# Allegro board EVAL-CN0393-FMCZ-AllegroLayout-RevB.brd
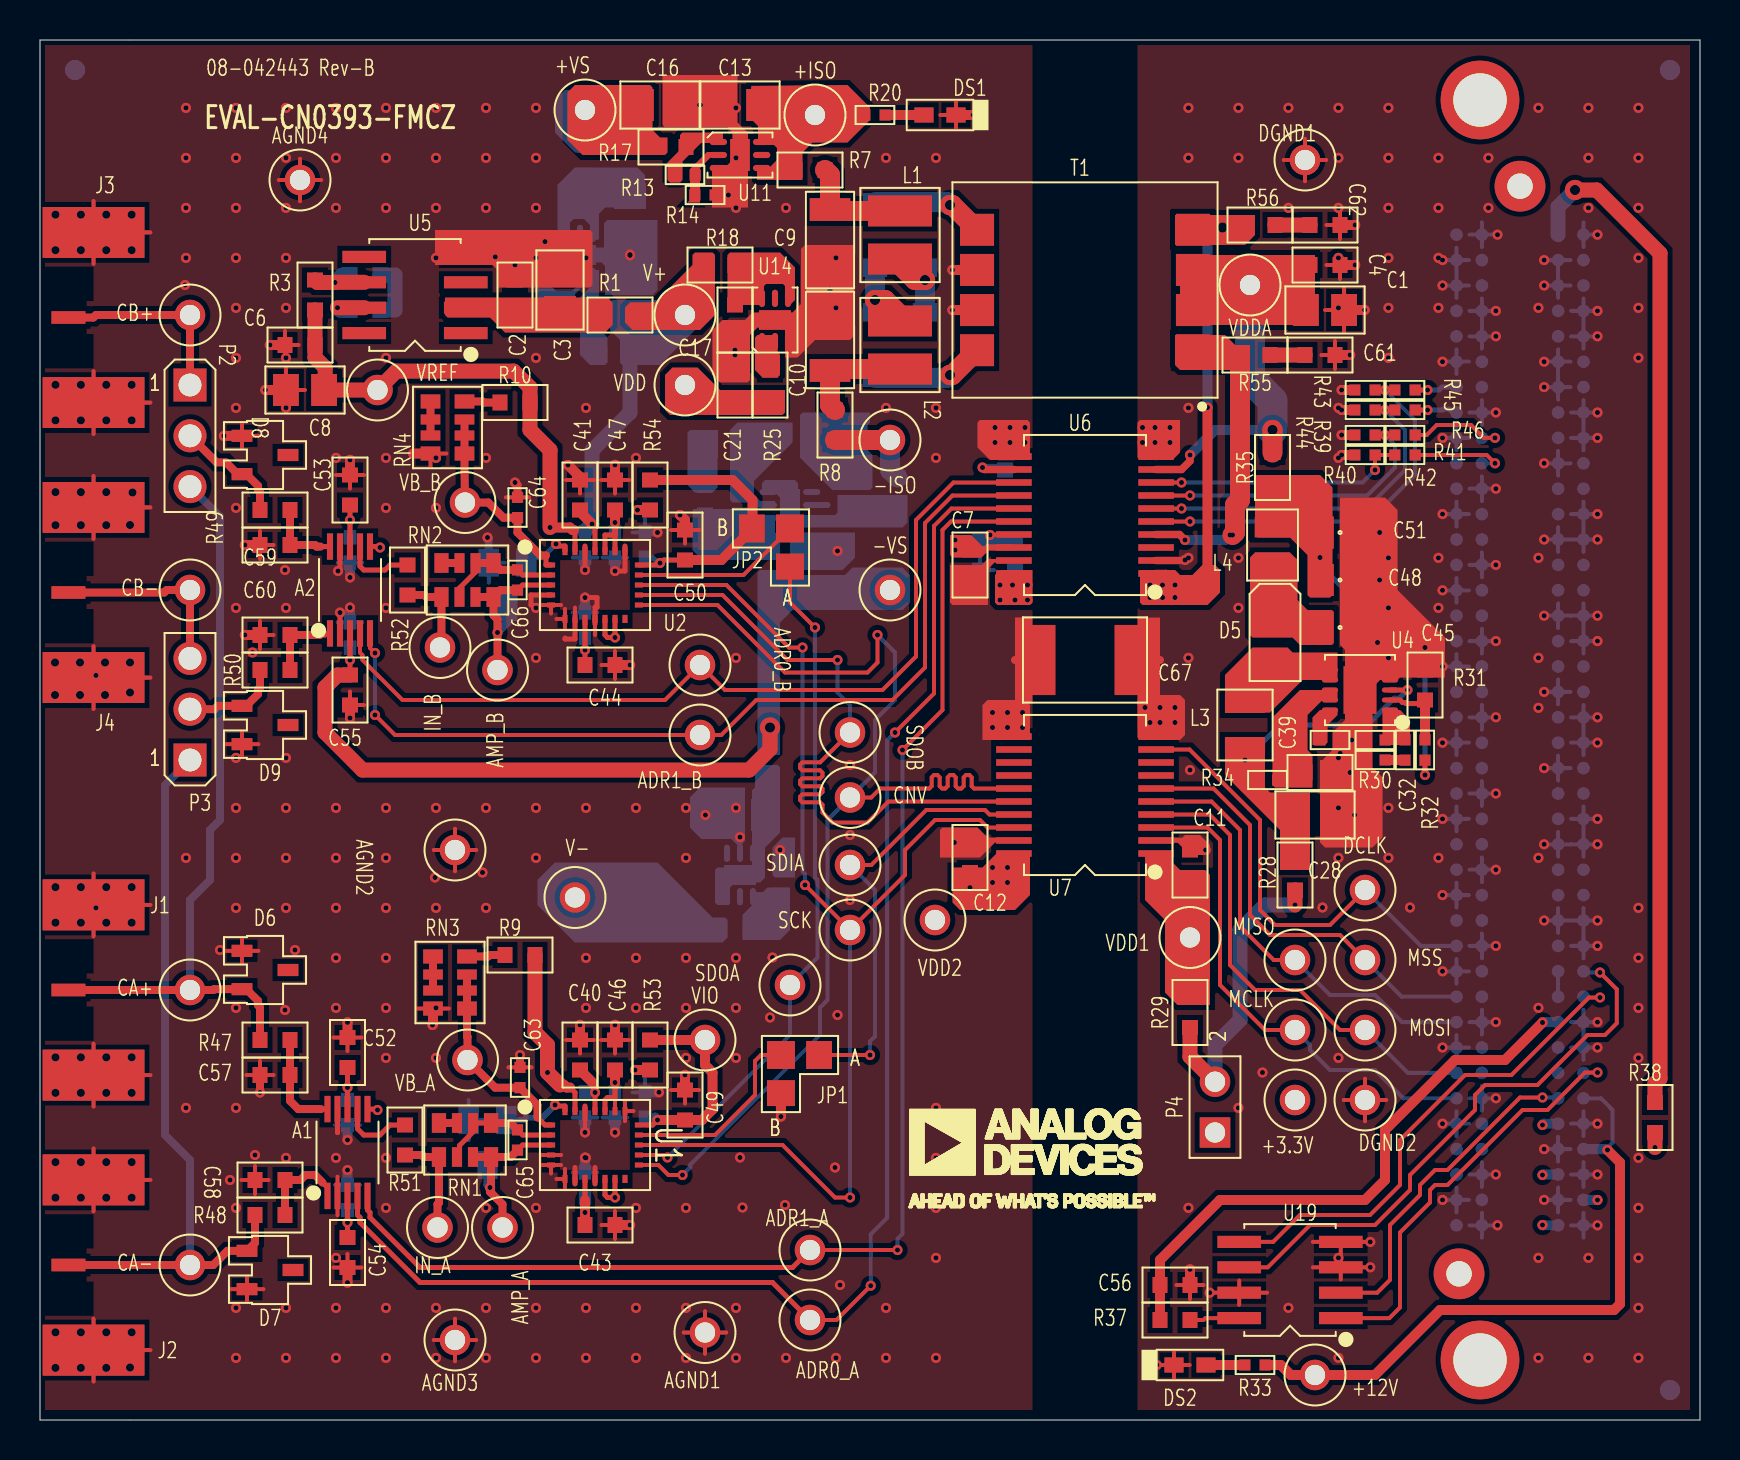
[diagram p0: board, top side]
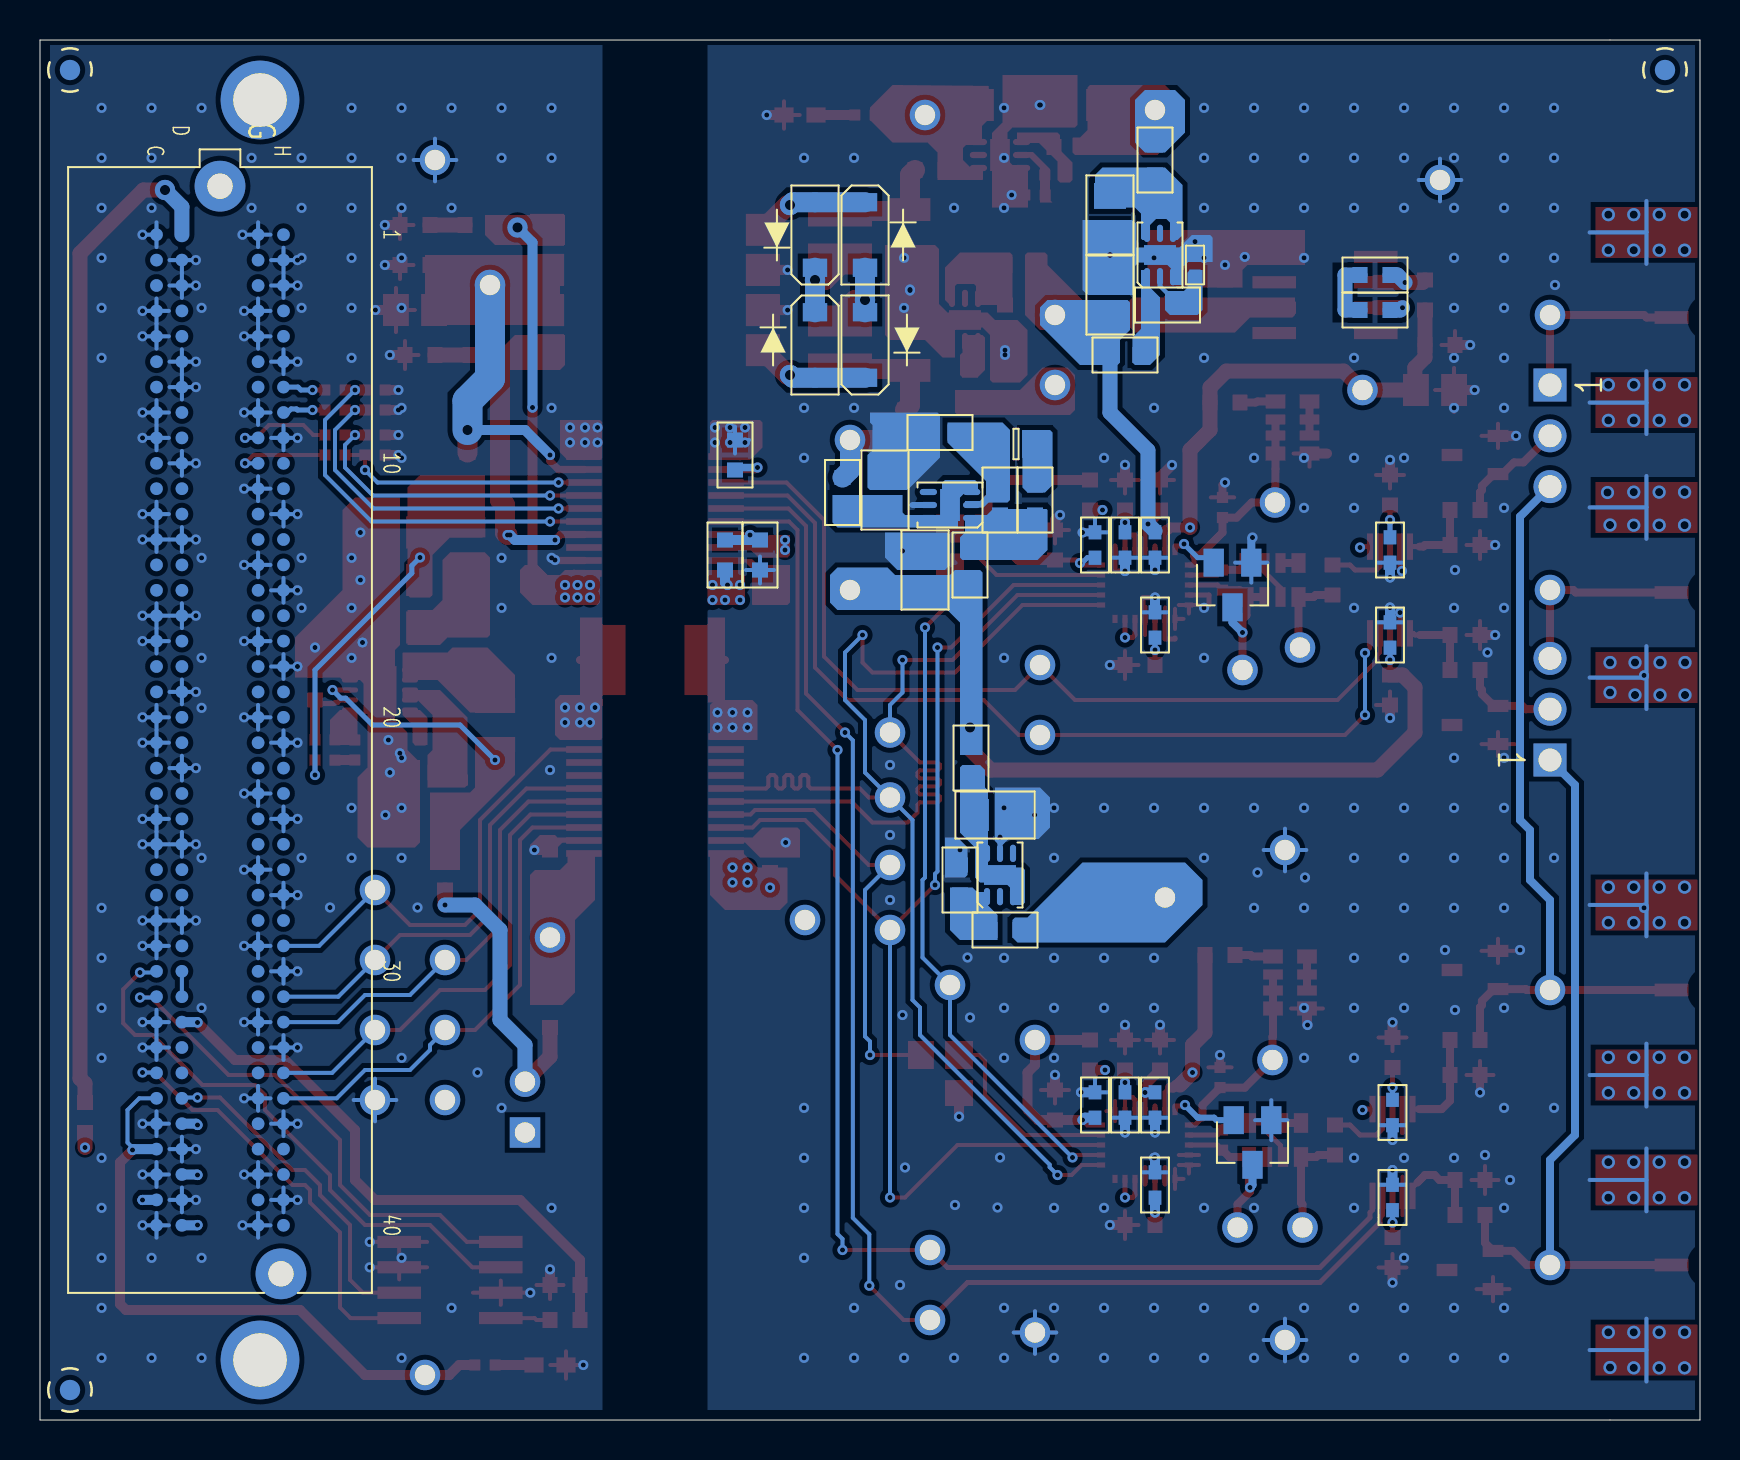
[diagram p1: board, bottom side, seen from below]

Outline 83 x 69 mm; copper layers: TOP, LAYER2, LAYER3, BOTTOM. Coordinates in mm from the lower left corner of the outline.
Outline path: 0,69 0,0 83,0 83,69 0,69

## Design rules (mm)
constraint set DEFAULT: 

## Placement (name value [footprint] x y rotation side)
A1  AD8251ARMZ  [RM10]  15.38 13.38 0 top
A2  AD8251ARMZ  [RM10]  15.5 41.5 0 top
ADR0_A  RED  [CNKEY5001TP]  38.5 5 0 top
ADR0_B  RED  [CNKEY5001TP]  33 37.75 0 top
ADR1_A  RED  [CNKEY5001TP]  38.5 8.5 0 top
ADR1_B  RED  [CNKEY5001TP]  33 34.25 0 top
AGND1  BLK  [CNKEY5001TP]  33.25 4.38 0 top
AGND2  BLK  [CNKEY5001TP]  20.75 28.5 0 top
AGND3  BLK  [CNKEY5001TP]  20.75 4 0 top
AGND4  BLK  [CNKEY5001TP]  13 62 0 top
AMP_A  RED  [CNKEY5001TP]  23.12 9.62 0 top
AMP_B  RED  [CNKEY5001TP]  22.88 37.5 0 top
C1  10uF  [C0805H53]  64.25 55.5 0 top
C2  0.1uF  [C0603]  23.75 56.25 90 top
C3  10uF  [C0805H53]  26 56.5 90 top
C4  0.1uF  [C0603]  64.25 57.75 0 top
C5  0.0027uF  [C0603]  16.25 57.25 0 bottom
C6  0.1uF  [C0603]  13 53.75 180 top
C7  0.1uF  [C0603]  46.5 42.75 270 top
C8  10uF  [C0805H53]  13.25 51.5 180 top
C9  47uF  [C1206H71]  39.5 59 270 top
C10  47uF  [C1206H71]  39.5 54 270 top
C11  0.1uF  [C0603]  57.5 27.75 90 top
C12  0.1uF  [C0603]  46.5 28.12 270 top
C13  10UF  [C0805H53]  35 65.75 180 top
C14  10UF  [C0805H53]  40.75 46.5 90 bottom
C15  0.1uF  [C0603]  33.25 46 270 bottom
C16  10UF  [C0805H53]  31 65.75 0 top
C17  4.7uF  [C0603]  34.75 55 270 top
C18  10UF  [C0805H53]  38.75 42.5 90 bottom
C19  4.7uF  [C0805H53]  29.5 60.25 270 bottom
C20  1uF  [C0805H53]  35.25 30.25 180 bottom
C21  4.7uF  [C0603]  34.75 51.75 90 top
C22  4.7uF  [C0603]  37 27 90 bottom
C23  10UF  [C0805H53]  29.5 56.25 90 bottom
C24  0.1uF  [C0402_A]  27.25 15.75 270 bottom
C25  0.1uF  [C0402_A]  27.25 43.75 270 bottom
C26  0.1uF  [C0402_A]  27.25 11.75 90 bottom
C27  0.1uF  [C0402_A]  27.25 39.75 90 bottom
C28  10UF  [C0805H53]  63.75 30.25 0 top
C29  10pF  [C0402]  66.75 34 0 top
C30  0.1uF  [C0402_A]  28.75 15.75 270 bottom
C31  0.1uF  [C0402_A]  28.75 43.75 270 bottom
C32  0.0068uF  [C0402]  68.25 33.5 270 top
C33  0.1uF  [C0402_A]  30.25 15.75 90 bottom
C34  0.1uF  [C0402_A]  30.25 43.75 90 bottom
C35  0.1uF  [C0402_A]  15.38 15.38 270 bottom
C36  0.1uF  [C0402_A]  15.5 43.5 270 bottom
C37  0.1uF  [C0402_A]  15.38 11.12 90 bottom
C38  0.1uF  [C0402_A]  15.5 39.25 90 bottom
C39  1uF  [C0603]  64 32.38 0 top
C40  10uF  [C0603]  27 18.25 90 top
C41  10uF  [C0603]  27 46.25 90 top
C42  0.01UF  [C0402]  64.5 34 0 top
C43  10uF  [C0603]  28 9.75 0 top
C44  10uF  [C0603]  28 37.75 0 top
C45  0.47uF  [C0805]  65 39.62 0 top
C46  10uF  [C0603]  28.75 18.25 90 top
C47  10uF  [C0603]  28.75 46.25 90 top
C48  10uF  [C0805]  65 42 0 top
C49  10uF  [C0603]  32.25 15.75 90 top
C50  10uF  [C0603]  32.25 43.75 90 top
C51  10uF  [C0805]  65 44.38 0 top
C52  10uF  [C0603]  15.38 18.38 90 top
C53  10uF  [C0603]  15.5 46.5 90 top
C54  10uF  [C0603]  15.38 8.38 270 top
C55  10uF  [C0603]  15.5 36.5 270 top
C56  0.1uF  [C0603]  56.75 6.75 0 top
C57  2.2uF  [C0603]  11.75 17.25 180 top
C58  2.2uF  [C0603]  11.5 12 180 top
C59  2.2uF  [C0603]  11.75 43.75 180 top
C60  2.2uF  [C0603]  11.75 39.25 180 top
C61  330pF  [C0603]  64 53.25 0 top
C62  330pF  [C0603]  64.25 59.75 0 top
C63  1.5PF  [C0402]  24 17.12 90 top
C64  1.5PF  [C0402]  23.88 45.62 90 top
C65  1.5PF  [C0402]  23.88 14 270 top
C66  1.5PF  [C0402]  23.88 42 270 top
C67  100PF  [C1812H63]  52.25 38 180 top
CA+  RED  [CNKEY5001TP]  7.5 21.5 0 top
CA-  RED  [CNKEY5001TP]  7.5 7.75 0 top
CB+  RED  [CNKEY5001TP]  7.5 55.25 0 top
CB-  RED  [CNKEY5001TP]  7.5 41.5 0 top
CNV  RED  [CNKEY5001TP]  40.5 31.12 0 top
CR1  BAT54S  [SOT23]  22.38 13.88 0 bottom
CR2  BAT54S  [SOT23]  23.38 41.75 0 bottom
D1  MBR0540T1G  [SOD123-2]  44.25 53.75 270 bottom
D2  MBR0540T1G  [SOD123-2]  41.75 53.75 90 bottom
D3  MBR0540T1G  [SOD123-2]  44.25 59.25 90 bottom
D4  MBR0540T1G  [SOD123-2]  41.75 59.25 270 bottom
D5  DFLS220L-7  [DSML110W70H39]  61.75 39.38 270 top
D6  MMBZ15VDL-7-F  [SOT23_B]  11.25 22.5 270 top
D7  MMBZ15VDL-7-F  [SOT23_B]  11.5 7.5 270 top
D8  MMBZ15VDL-7-F  [SOT23_B]  11.25 48.25 270 top
D9  MMBZ15VDL-7-F  [SOT23_B]  11.25 34.75 270 top
DCLK  RED  [CNKEY5001TP]  66.25 26.5 0 top
DGND1  BLK  [CNKEY5001TP]  63.25 63 0 top
DGND2  BLK  [CNKEY5001TP]  66.25 16 0 top
DS1  SML-310MTT86  [LED0603]  45 65.25 180 top
DS2  SML-310MTT86  [LED0603]  57.5 2.75 0 top
IN_A  RED  [CNKEY5001TP]  19.88 9.62 0 top
IN_B  RED  [CNKEY5001TP]  20 38.62 0 top
J1  142-0701-851  [CNSMAL562W375H166]  2.5 21.5 180 top
J2  142-0701-851  [CNSMAL562W375H166]  2.5 7.75 180 top
J3  142-0701-851  [CNSMAL562W375H166]  2.5 55.12 180 top
J4  142-0701-851  [CNSMAL562W375H166]  2.5 41.38 180 top
JP1  3PIN_JUMPER_SM  [3PINJUMPER_0603]  38 18.25 180 top
JP2  3PIN_JUMPER_SM  [3PINJUMPER_0603]  37.5 43.62 90 top
L1  47UH  [L1212H59_A]  43 59.25 90 top
L2  47UH  [L1212H59_A]  43 53.75 270 top
L3  1UH  [L1008H47]  60.25 34.75 90 top
L4  110nH  [L9075]  61.62 43.75 90 top
MCLK  RED  [CNKEY5001TP]  62.75 19.5 0 top
MISO  RED  [CNKEY5001TP]  62.75 23 0 top
MOSI  RED  [CNKEY5001TP]  66.25 19.5 0 top
MSS  RED  [CNKEY5001TP]  66.25 23 0 top
NOREF  -  []  0 69 0 top
NOREF#2  -  [unnamed#2]  72 66 0 top
NOREF#3  -  []  -54 -78 0 top
NOREF#4  -  [unnamed#2]  72 3 0 top
NOREF#5  -  []  0 0 90 top
NOREF#6  -  []  58 -10.5 0 top
NOREF#7  -  []  -54 -78 0 top
NOREF#8  -  [unnamed#2]  81.5 1.5 180 bottom
NOREF#9  -  [unnamed#2]  81.5 67.5 180 bottom
NOREF#10  -  [unnamed#2]  1.75 67.5 180 bottom
P1  ASP-134604-01  [CNSAMTECASP-134604-01]  74 34.5 270 bottom
P2  TSW-103-08-G-S  [CNBERG1X3H205LD36]  7.5 51.75 270 top
P3  TSW-103-08-G-S  [CNBERG1X3H205LD36]  7.5 33 90 top
P4  69157-102HLF  [CNBERG69157-102]  58.75 14.38 90 top
R1  0  [R0603]  29 55.25 180 top
R2  0  [R0603]  16.25 55.5 0 bottom
R3  0  [R0603]  13.75 56.25 270 top
R4  100K  [R0603]  48.25 48.25 90 bottom
R5  100K  [R0603]  48.75 43.25 90 bottom
R6  8.2K  [R0603]  47 43.25 270 bottom
R7  0  [R0603]  38.5 62.5 180 top
R8  0  [R0603]  39.75 49.75 270 top
R9  0  [R0603]  24 23.25 180 top
R10  0  [R0603]  23.75 50.88 180 top
R11  0  [R0603]  42.88 46.38 270 bottom
R12  13.3K  [R0603]  38 49.38 180 bottom
R13  100K  [R0402]  32.25 62.25 180 top
R14  49.9K  [R0402]  33.25 61.25 0 top
R15  13K  [R0805]  34.2 48.8 180 bottom
R16  150K  [R0603]  35 46 270 bottom
R17  0  [R0603]  31.55 63.65 180 top
R18  0  [R0603]  34 57.75 0 top
R19  0  [R0603]  36.5 42.75 270 bottom
R20  100K  [R0402]  41.75 65.25 0 top
R21  0  [R0603]  27.25 63 270 bottom
R22  0  [R0603]  36.45 33.1 270 bottom
R23  25K  [R0603]  26.62 55.75 0 bottom
R24  49.9K  [R0402]  25.25 57.75 90 bottom
R25  0  [R0603]  36.5 51.75 270 top
R26  0  [R0603]  28.75 53.25 0 bottom
R27  0  [R0603]  34.75 24.5 180 bottom
R28  0  [R0603]  62.75 27.25 90 top
R29  0  [R0603]  57.5 20.38 90 top
R30  2.94K  [R0402]  66.75 33 0 top
R31  31.6K  [R0603]  69.25 36.75 270 top
R32  95.3K  [R0402]  69.25 33.5 270 top
R33  49.9K  [R0402]  60.75 2.75 0 top
R34  1  [R0402]  61.38 32 0 top
R35  0  [R0603]  61.62 47.62 90 top
R37  0  [R0603]  56.75 5 180 top
R38  10K  [R0603]  80.75 15.12 90 top
R39  0  [R0402]  66.25 49.25 0 top
R40  0  [R0402]  66.25 48.25 180 top
R41  0  [R0402]  68.25 49.25 0 top
R42  0  [R0402]  68.25 48.25 0 top
R43  0  [R0402]  66.25 51.5 0 top
R44  0  [R0402]  66.25 50.5 180 top
R45  0  [R0402]  68.25 51.5 0 top
R46  0  [R0402]  68.25 50.5 0 top
R47  0  [R0603]  11.75 19 0 top
R48  0  [R0603]  11.5 10.25 0 top
R49  0  [R0603]  11.75 45.5 0 top
R50  0  [R0603]  11.75 37.5 0 top
R51  0  [R0603]  18.25 14 270 top
R52  0  [R0603]  18.38 42 270 top
R53  0  [R0603]  30.5 18.25 90 top
R54  0  [R0603]  30.5 46.25 90 top
R55  14  [R0603]  60.75 53.25 0 top
R56  14  [R0603]  61 59.75 0 top
RN1  1K  [R1206-8P]  21.25 14 180 top
RN2  1K  [R1206-8P]  21.38 42 180 top
RN3  1K  [R1206-8P]  20.5 21.88 270 top
RN4  1K  [R1206-8P]  20.38 49.62 270 top
SCK  RED  [CNKEY5001TP]  40.5 24.5 0 top
SDIA  RED  [CNKEY5001TP]  40.5 27.75 0 top
SDOA  RED  [CNKEY5001TP]  37.5 21.75 0 top
SDOB  RED  [CNKEY5001TP]  40.5 34.38 0 top
T1  KA4976-AL  [TSML394W319H235]  52.25 56.5 90 top
U1  ADAQ7988BCCZ  [LGA24]  27.75 13.75 270 top
U2  ADAQ7988BCCZ  [LGA24]  27.75 41.75 270 top
U3  ADP7182ACPZN  [DFN6_2X2_PAD1_6X1]  37.5 45.75 90 bottom
U4  ADP1614ACPZ-R7  [QFN10_3X3_PAD2_38X1_64]  66 36.5 90 top
U5  ADR4550BRZ  [SO8]  18.75 56.25 90 top
U6  ADUM3470ARSZ  [SSOP20-4]  52.25 45.25 90 top
U7  ADUM3150ARSZ  [SSOP20-4]  52.25 31.25 90 top
U11  ADP7118ACPZN-5.0  [DFN6_2X2_PAD1_6X1]  35 63.25 270 top
U13  ADP7118ACPZN-5.0  [DFN6_2X2_PAD1_6X1]  27 58.25 180 bottom
U14  ADP7118ACPZN-5.0  [DFN6_2X2_PAD1_6X1]  36.75 55 0 top
U17  ADP7182ACPZN-2.5  [DFN6_2X2_PAD1_6X1]  35 27.25 180 bottom
U19  M24C02-RMN6TP  [SO8]  62.5 7 90 top
UNK+3.3V  RED  [CNKEY5001TP]  62.75 16 0 top
UNK+12V  RED  [CNKEY5001TP]  63.75 2.25 0 top
UNK+ISO  RED  [CNKEY5001TP]  38.75 65.25 0 top
UNK+VS  RED  [CNKEY5001TP]  27.25 65.5 0 top
UNK-ISO  RED  [CNKEY5001TP]  42.5 49 0 top
UNK-VS  RED  [CNKEY5001TP]  42.5 41.5 0 top
V+  RED  [CNKEY5001TP]  32.25 55.25 0 top
V-  RED  [CNKEY5001TP]  26.75 26.12 0 top
VB_A  RED  [CNKEY5001TP]  21.38 18 0 top
VB_B  RED  [CNKEY5001TP]  21.25 45.88 0 top
VDD  RED  [CNKEY5001TP]  32.25 51.75 0 top
VDD1  RED  [CNKEY5001TP]  57.5 24.12 0 top
VDD2  RED  [CNKEY5001TP]  44.75 25 0 top
VDDA  RED  [CNKEY5001TP]  60.5 56.75 0 top
VIO  RED  [CNKEY5001TP]  33.25 19 0 top
VREF  RED  [CNKEY5001TP]  16.88 51.5 0 top

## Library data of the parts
A1 A2 = AD8251: User Part Number: UPN; Tolerance: N/A; alternate symbols: (); part number: AD8251_SM-AD8251ARMZ,E019018,RM10; tolerance: N/A
ADR0_A ADR0_B ADR1_A ADR1_B AMP_A AMP_B CA+ CA- CB+ CB- CNV DCLK IN_A IN_B MCLK MISO MOSI MSS SCK SDIA SDOA SDOB UNK+3.3V UNK+12V UNK+ISO UNK+VS UNK-ISO UNK-VS V+ V- VB_A VB_B VDD VDD1 VDD2 VDDA VIO VREF = CNTP1P: Tolerance: N/A; User Part Number: UPN; alternate symbols: (); part number: CNTP1P_TH-RED,E019485,CNKEY5001TP; tolerance: N/A
AGND1-AGND4 DGND1 DGND2 = CNTP1P: Tolerance: N/A; User Part Number: UPN; alternate symbols: (); part number: CNTP1P_TH-BLK,E019484,CNKEY5001TP; tolerance: N/A
C1 C3 C8 = CAP: User Part Number: UPN; Tolerance: 10; alternate symbols: (); part number: CAP_SM-10UF,16V,10,E006166,C0805H53; tolerance: 10
C2 C4 C6 C7 C11 C12 C56 = CAP: User Part Number: UPN; Tolerance: 10; alternate symbols: (); part number: CAP_SM-0.1UF,16V,10,E015036,C0603; tolerance: 10
C5 = CAP: User Part Number: UPN; Tolerance: 10; alternate symbols: (); part number: CAP_SM-0.0027UF,50V,10,E015578,C0603; tolerance: 10
C9 C10 = CAP: User Part Number: UPN; Tolerance: 20; alternate symbols: (); part number: CAP_SM-47UF,25V,20,E019173,C1206H71; tolerance: 20
C13 C14 C16 C18 C23 C28 = CAP: User Part Number: UPN; Tolerance: 10; alternate symbols: (); part number: CAP_SM-10UF,35V,10,E025307,C0805H53; tolerance: 10
C15 = CAP: User Part Number: UPN; Tolerance: 10; alternate symbols: (); part number: CAP_SM-0.1UF,25V,10,E013746,C0603; tolerance: 10
C17 C21 C22 = CAP: User Part Number: UPN; Tolerance: 10; alternate symbols: (); part number: CAP_SM-4.7UF,16V,10,E020112,C0603; tolerance: 10
C19 = CAP: User Part Number: UPN; Tolerance: 10; alternate symbols: (); part number: CAP_SM-4.7UF,25V,10,E006908,C0805H53; tolerance: 10
C20 = CAP: User Part Number: UPN; Tolerance: 10; alternate symbols: (); part number: CAP_SM-1UF,25V,10,E023500,C0805H53; tolerance: 10
C24-C27 C30 C31 C33-C38 = CAP: Tolerance: 10; User Part Number: UPN; alternate symbols: (); part number: CAP_SM-0.1UF,25V,10,E020372,C0402_A; tolerance: 10
C29 = CAP: User Part Number: UPN; Tolerance: 5; alternate symbols: (); part number: CAP_SM-10PF,50V,5,E007982,C0402; tolerance: 5
C32 = CAP: User Part Number: UPN; Tolerance: 10; alternate symbols: (); part number: CAP_SM-0.0068UF,25V,10,E012594,C0402; tolerance: 10
C39 = CAP: User Part Number: UPN; Tolerance: 10; alternate symbols: (); part number: CAP_SM-1UF,10V,10,E011783,C0603; tolerance: 10
C40 C41 C43 C44 C46 C47 C49 C50 C52-C55 = CAP: User Part Number: UPN; Tolerance: 20; alternate symbols: (); part number: CAP_SM-10UF,25V,20,E023693,C0603; tolerance: 20
C42 = CAP: User Part Number: UPN; Tolerance: 10; alternate symbols: (); part number: CAP_SM-0.01UF,25V,10,E013688,C0402; tolerance: 10
C45 = CAP: User Part Number: UPN; Tolerance: 10; alternate symbols: (); part number: CAP_SM-0.47UF,16V,10,E000566,C0805; tolerance: 10
C48 C51 = CAP: User Part Number: UPN; Tolerance: 10; alternate symbols: (); part number: CAP_SM-10UF,25V,10,E019080,C0805; tolerance: 10
C57-C60 = CAP: User Part Number: UPN; Tolerance: 10; alternate symbols: (); part number: CAP_SM-2.2UF,6.3V,10,E006877,C0603; tolerance: 10
C61 C62 = CAP: User Part Number: UPN; Tolerance: 5; alternate symbols: (); part number: CAP_SM-330PF,50V,5,E012696,C0603; tolerance: 5
C63-C66 = CAP: User Part Number: UPN; Tolerance: 0.25PF; alternate symbols: (); part number: CAP_SM-1.5PF,50V,0.25PF,E000262,C0402; tolerance: 0.25PF
C67 = CAP: Tolerance: 10; User Part Number: UPN; alternate symbols: (); part number: CAP_SM-100PF,3000V,10,E026062,C1812H63; tolerance: 10
CR1 CR2 = DIOHSMS28X2: User Part Number: UPN; Tolerance: N/A; alternate symbols: (); part number: DIOHSMS28X2_SM-BAT54S,30V,N/A,E006846,SOT23; tolerance: N/A
D1-D4 = DIOSCHOTTKY: User Part Number: UPN; Tolerance: N/A; alternate symbols: (); part number: DIOSCHOTTKY_SM-MBR0540T1G,40V,N/A,E011535,SOD123-2; tolerance: N/A
D5 = DIOSCHOTTKY: User Part Number: UPN; Tolerance: N/A; alternate symbols: (); part number: DIOSCHOTTKY_SM-DFLS220L-7,20V,N/A,E010878,DSML110W70H39; tolerance: N/A
D6-D9 = DIOTVS3P: User Part Number: UPN; Tolerance: N/A; alternate symbols: (); part number: DIOTVS3P_SM-MMBZ15VDL-7-F,12.8V,N/A,E025412,SOT23_B; tolerance: N/A
DS1 DS2 = DIOLED: User Part Number: UPN; Tolerance: N/A; alternate symbols: (); part number: DIOLED_SM-SML-310MTT86,2.8V,N/A,E001179,LED0603; tolerance: N/A
J1-J4 = CNBNC5P: Tolerance: N/A; User Part Number: UPN; alternate symbols: (); part number: CNBNC5P_SM-142-0701-851,E014551,CNSMAL562W375H166; tolerance: N/A
JP1 JP2 = NC3P_JMPR: User Part Number: UPN; Tolerance: N/A; alternate symbols: (); part number: NC3P_JMPR_SM-3PIN_JUMPER_SM,E008052,3PINJUMPER_0603; tolerance: N/A
L1 L2 = IND: User Part Number: UPN; Tolerance: 20; alternate symbols: (); part number: IND_SM-47UH,20,E017337,L1212H59_A; tolerance: 20
L3 = IND: Tolerance: 20; User Part Number: UPN; alternate symbols: (); part number: IND_SM-1UH,20,E025308,L1008H47; tolerance: 20
L4 = IND: Tolerance: 5; User Part Number: UPN; alternate symbols: (); part number: IND_SM-110NH,5,E016398,L9075; tolerance: 5
P1 = CN160P_CDGH: User Part Number: UPN; Tolerance: N/A; alternate symbols: (CNSAMTECASP-134604-01_KITTRF); part number: CN160P_CDGH_SM-ASP-134604-01,E011383,CNSAMTECASP-134604-01; tolerance: N/A
P2 P3 = CN3P: Tolerance: N/A; User Part Number: UPN; alternate symbols: (); part number: CN3P_TH-TSW-103-08-G-S,E000812,CNBERG1X3H205LD36; tolerance: N/A
P4 = CN2P: User Part Number: UPN; Tolerance: N/A; alternate symbols: (); part number: CN2P_TH-69157-102HLF,E000791,CNBERG69157-102; tolerance: N/A
R1-R3 R7-R11 R17-R19 R21 R22 R25-R29 R35 R37 R47-R54 = RES: User Part Number: UPN; Tolerance: 1; alternate symbols: (); part number: RES_SM-0,E004207,1/16W,1,R0603; tolerance: 1
R4 R5 = RES: User Part Number: UPN; Tolerance: 1; alternate symbols: (); part number: RES_SM-100K,E010279,1/10W,1,R0603; tolerance: 1
R6 = RES: User Part Number: UPN; Tolerance: 1; alternate symbols: (); part number: RES_SM-8.2K,E004253,1/16W,1,R0603; tolerance: 1
R12 = RES: User Part Number: UPN; Tolerance: 1; alternate symbols: (); part number: RES_SM-13.3K,E008069,1/10W,1,R0603; tolerance: 1
R13 R20 = RES: User Part Number: UPN; Tolerance: 5; alternate symbols: (); part number: RES_SM-100K,E003464,1/10W,5,R0402; tolerance: 5
R14 R24 R33 = RES: User Part Number: UPN; Tolerance: 1; alternate symbols: (); part number: RES_SM-49.9K,E004901,1/16W,1,R0402; tolerance: 1
R15 = RES: User Part Number: UPN; Tolerance: 1; alternate symbols: (); part number: RES_SM-13K,E003507,1/8W,1,R0805; tolerance: 1
R16 = RES: User Part Number: UPN; Tolerance: 1; alternate symbols: (); part number: RES_SM-150K,E003672,1/10W,1,R0603; tolerance: 1
R23 = RES: User Part Number: UPN; Tolerance: 0.1; alternate symbols: (); part number: RES_SM-25K,E018041,0.15W,0.1,R0603; tolerance: 0.1
R30 = RES: User Part Number: UPN; Tolerance: 1; alternate symbols: (); part number: RES_SM-2.94K,E018093,1/10W,1,R0402; tolerance: 1
R31 = RES: User Part Number: UPN; Tolerance: 1; alternate symbols: (); part number: RES_SM-31.6K,E013702,1/10W,1,R0603; tolerance: 1
R32 = RES: User Part Number: UPN; Tolerance: 1; alternate symbols: (); part number: RES_SM-95.3K,E006343,1/16W,1,R0402; tolerance: 1
R34 = RES: User Part Number: UPN; Tolerance: 5; alternate symbols: (); part number: RES_SM-1,E010031,1/16W,5,R0402; tolerance: 5
R38 = RES: User Part Number: UPN; Tolerance: 1; alternate symbols: (); part number: RES_SM-10K,E003671,1/10W,1,R0603; tolerance: 1
R39-R46 = RES: User Part Number: UPN; Tolerance: 5; alternate symbols: (); part number: RES_SM-0,E003438,N/A,5,R0402; tolerance: 5
R55 R56 = RES: User Part Number: UPN; Tolerance: 1; alternate symbols: (); part number: RES_SM-14,E025536,1/10W,1,R0603; tolerance: 1
RN1-RN4 = RESNET_8P_4R: Tolerance: 0.1; User Part Number: UPN; alternate symbols: (); part number: RESNET_8P_4R_SM-1K,E024992,1/10W,0.1,R1206-8P; tolerance: 0.1
T1 = XFMRKA4976: Tolerance: N/A; User Part Number: UPN; alternate symbols: (); part number: XFMRKA4976_SM-KA4976-AL,E017329,TSML394W319H235; tolerance: N/A
U1 U2 = ADAQ798X: Tolerance: N/A; User Part Number: UPN; alternate symbols: (); part number: ADAQ798X_SM-ADAQ7988BCCZ,E028182,LGA24; tolerance: N/A
U3 = ADP7182_V5: Tolerance: N/A; User Part Number: UPN; alternate symbols: (); part number: ADP7182_V5_SM-ADP7182ACPZN,E024308,DFN6_2X2_PAD1_6X1; tolerance: N/A
U4 = ADP1614: User Part Number: UPN; Tolerance: N/A; alternate symbols: (); part number: ADP1614_SM-ADP1614ACPZ-R7,E025247,QFN10_3X3_PAD2_38X1_64; tolerance: N/A
U5 = ADR45XX: User Part Number: UPN; Tolerance: N/A; alternate symbols: (); part number: ADR45XX_SM-ADR4550BRZ,E016255,SO8; tolerance: N/A
U6 = ADUM3470: Tolerance: N/A; User Part Number: UPN; alternate symbols: (); part number: ADUM3470_SM-ADUM3470ARSZ,E024958,SSOP20-4; tolerance: N/A
U7 = ADUM3150: Tolerance: N/A; User Part Number: UPN; alternate symbols: (); part number: ADUM3150_SM-ADUM3150ARSZ,E021747,SSOP20-4; tolerance: N/A
U11 U13 U14 = ADP7118: Tolerance: N/A; User Part Number: UPN; alternate symbols: (); part number: ADP7118_SM-ADP7118ACPZN-5.0,E021288,DFN6_2X2_PAD1_6X1; tolerance: N/A
U17 = ADP7182_V6: Tolerance: N/A; User Part Number: UPN; alternate symbols: (); part number: ADP7182_V6_SM-ADP7182ACPZN-2.5,E024945,DFN6_2X2_PAD1_6X1; tolerance: N/A
U19 = ICM24CXX: User Part Number: UPN; Tolerance: N/A; alternate symbols: (); part number: ICM24CXX_SM-M24C02-RMN6TP,E018349,SO8; tolerance: N/A

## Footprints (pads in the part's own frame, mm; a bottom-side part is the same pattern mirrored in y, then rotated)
3PINJUMPER_0603
  rect 1.295x1.397 smd: 1(-0.953,0)
  rect 1.397x1.397 smd: 2(0.953,0)
  rect 1.397x1.295 smd: 3(0.953,1.905)
C0402
  rect 0.559x0.559 smd: 1(-0.508,0) 2(0.508,0)
C0402_A
  rect 0.711x0.635 smd: 1(-0.635,0) 2(0.635,0)
C0603
  rect 0.75x0.8 smd: 1(-0.75,0) 2(0.75,0)
C0805
  rect 1.295x1.6 smd: 1(-0.953,0) 2(0.953,0)
C0805H53
  rect 1.295x1.6 smd: 1(-0.953,0) 2(0.953,0)
C1206H71
  rect 1.143x2.032 smd: 1(-1.524,0) 2(1.524,0)
C1812H63
  rect 1.245x3.505 smd: 1(-2.1,0) 2(2.1,0)
CNBERG1X3H205LD36
  rect 1.651x1.651 hole 1.143: 1(0,0)
  round 1.651 hole 1.143: 2(2.54,0) 3(5.08,0)
CNBERG69157-102
  rect 1.524x1.524 hole 1.016: 1(0,0)
  round 1.524 hole 1.016: 2(2.54,0)
CNKEY5001TP
  round 1.524 hole 1.016: 1(0,0)
CNSAMTECASP-134604-01
  round 2.54 hole 1.27 unplated: (-27.191,0) (27.191,3.048)
  round 0.635 smd: C1(-24.765,-3.175) C2(-23.495,-3.175) C3(-22.225,-3.175) C4(-20.955,-3.175) C5(-19.685,-3.175) C6(-18.415,-3.175) C7(-17.145,-3.175) C8(-15.875,-3.175) C9(-14.605,-3.175) C10(-13.335,-3.175) C11(-12.065,-3.175) C12(-10.795,-3.175) C13(-9.525,-3.175) C14(-8.255,-3.175) C15(-6.985,-3.175) C16(-5.715,-3.175) C17(-4.445,-3.175) C18(-3.175,-3.175) C19(-1.905,-3.175) C20(-0.635,-3.175) C21(0.635,-3.175) C22(1.905,-3.175) C23(3.175,-3.175) C24(4.445,-3.175) C25(5.715,-3.175) C26(6.985,-3.175) C27(8.255,-3.175) C28(9.525,-3.175) C29(10.795,-3.175) C30(12.065,-3.175) C31(13.335,-3.175) C32(14.605,-3.175) C33(15.875,-3.175) C34(17.145,-3.175) C35(18.415,-3.175) C36(19.685,-3.175) C37(20.955,-3.175) C38(22.225,-3.175) C39(23.495,-3.175) C40(24.765,-3.175) D1(-24.765,-1.905) D2(-23.495,-1.905) D3(-22.225,-1.905) D4(-20.955,-1.905) D5(-19.685,-1.905) D6(-18.415,-1.905) D7(-17.145,-1.905) D8(-15.875,-1.905) D9(-14.605,-1.905) D10(-13.335,-1.905) D11(-12.065,-1.905) D12(-10.795,-1.905) D13(-9.525,-1.905) D14(-8.255,-1.905) D15(-6.985,-1.905) D16(-5.715,-1.905) D17(-4.445,-1.905) D18(-3.175,-1.905) D19(-1.905,-1.905) D20(-0.635,-1.905) D21(0.635,-1.905) D22(1.905,-1.905) D23(3.175,-1.905) D24(4.445,-1.905) D25(5.715,-1.905) D26(6.985,-1.905) D27(8.255,-1.905) D28(9.525,-1.905) D29(10.795,-1.905) D30(12.065,-1.905) D31(13.335,-1.905) D32(14.605,-1.905) D33(15.875,-1.905) D34(17.145,-1.905) D35(18.415,-1.905) D36(19.685,-1.905) D37(20.955,-1.905) D38(22.225,-1.905) D39(23.495,-1.905) D40(24.765,-1.905) G1(-24.765,1.905) G2(-23.495,1.905) G3(-22.225,1.905) G4(-20.955,1.905) G5(-19.685,1.905) G6(-18.415,1.905) G7(-17.145,1.905) G8(-15.875,1.905) G9(-14.605,1.905) G10(-13.335,1.905) G11(-12.065,1.905) G12(-10.795,1.905) G13(-9.525,1.905) G14(-8.255,1.905) G15(-6.985,1.905) G16(-5.715,1.905) G17(-4.445,1.905) G18(-3.175,1.905) G19(-1.905,1.905) G20(-0.635,1.905) G21(0.635,1.905) G22(1.905,1.905) G23(3.175,1.905) G24(4.445,1.905) G25(5.715,1.905) G26(6.985,1.905) G27(8.255,1.905) G28(9.525,1.905) G29(10.795,1.905) G30(12.065,1.905) G31(13.335,1.905) G32(14.605,1.905) G33(15.875,1.905) G34(17.145,1.905) G35(18.415,1.905) G36(19.685,1.905) G37(20.955,1.905) G38(22.225,1.905) G39(23.495,1.905) G40(24.765,1.905) H1(-24.765,3.175) H2(-23.495,3.175) H3(-22.225,3.175) H4(-20.955,3.175) H5(-19.685,3.175) H6(-18.415,3.175) H7(-17.145,3.175) H8(-15.875,3.175) H9(-14.605,3.175) H10(-13.335,3.175) H11(-12.065,3.175) H12(-10.795,3.175) H13(-9.525,3.175) H14(-8.255,3.175) H15(-6.985,3.175) H16(-5.715,3.175) H17(-4.445,3.175) H18(-3.175,3.175) H19(-1.905,3.175) H20(-0.635,3.175) H21(0.635,3.175) H22(1.905,3.175) H23(3.175,3.175) H24(4.445,3.175) H25(5.715,3.175) H26(6.985,3.175) H27(8.255,3.175) H28(9.525,3.175) H29(10.795,3.175) H30(12.065,3.175) H31(13.335,3.175) H32(14.605,3.175) H33(15.875,3.175) H34(17.145,3.175) H35(18.415,3.175) H36(19.685,3.175) H37(20.955,3.175) H38(22.225,3.175) H39(23.495,3.175) H40(24.765,3.175)
CNSMAL562W375H166
  rect 1.702x0.635 smd: 1(1.079,0)
  rect 5.08x2.54 smd: 2(-0.178,4.255) 3(-0.178,4.255) 4(-0.178,-4.255) 5(-0.178,-4.255)
DFN6_2X2_PAD1_6X1
  oval 0.305x0.864 smd: 1(-0.65,-1.082) 2(0,-1.082) 3(0.65,-1.082) 4(0.65,1.082) 5(0,1.082) 6(-0.65,1.082)
  rect 1.6x0.991 smd: PAD(0,0)
DSML110W70H39
  rect 0.889x1.397 smd: A(1.605,0)
  rect 2.21x1.397 smd: C(-0.945,0)
L1008H47
  rect 0.787x2.007 smd: 1(-0.994,0) 2(0.994,0)
L1212H59_A
  rect 1.549x3.2 smd: 1(-1.2,0) 2(1.2,0)
L9075
  rect 1.016x1.778 smd: 1(-0.889,0) 2(0.889,0)
LED0603
  rect 0.965x0.762 smd: A(0.8,0) C(-0.8,0)
LGA24
  rect 0.254x0.406 smd: 1(-1,-2.197) 2(-0.5,-2.197) 3(0,-2.197) 4(0.5,-2.197) 5(1,-2.197) 13(1,2.197) 14(0.5,2.197) 15(0,2.197) 16(-0.5,2.197) 17(-1,2.197)
  rect 0.406x0.254 smd: 6(1.697,-1.5) 7(1.697,-1) 8(1.697,-0.5) 9(1.697,0) 10(1.697,0.5) 11(1.697,1) 12(1.697,1.5) 18(-1.697,1.5) 19(-1.697,1) 20(-1.697,0.5) 21(-1.697,0) 22(-1.697,-0.5) 23(-1.697,-1) 24(-1.697,-1.5)
QFN10_3X3_PAD2_38X1_64
  oval 0.254x0.813 smd: 1(-1,-1.5) 2(-0.5,-1.5) 3(0,-1.5) 4(0.5,-1.5) 5(1,-1.5) 6(1,1.5) 7(0.5,1.5) 8(0,1.5) 9(-0.5,1.5) 10(-1,1.5)
  rect 2.388x1.651 smd: PAD(0,0)
R0402
  rect 0.559x0.559 smd: 1(-0.508,0) 2(0.508,0)
R0603
  rect 0.75x0.8 smd: 1(-0.75,0) 2(0.75,0)
R0805
  rect 1.295x1.397 smd: 1(-0.953,0) 2(0.953,0)
R1206-8P
  rect 0.711x0.991 smd: 1(-1.302,-0.85) 4(1.302,-0.85) 5(1.302,0.85) 8(-1.302,0.85)
  rect 0.508x0.991 smd: 2(-0.4,-0.85) 3(0.4,-0.85) 6(0.4,0.85) 7(-0.4,0.85)
RM10
  rect 0.305x1.321 smd: 1(-1,-2.171) 2(-0.5,-2.171) 3(0,-2.171) 4(0.5,-2.171) 5(1,-2.171) 6(1,2.171) 7(0.5,2.171) 8(0,2.171) 9(-0.5,2.171) 10(-1,2.171)
SO8
  rect 0.61x2.184 smd: 1(-1.905,-2.54) 2(-0.635,-2.54) 3(0.635,-2.54) 4(1.905,-2.54) 5(1.905,2.54) 6(0.635,2.54) 7(-0.635,2.54) 8(-1.905,2.54)
SOD123-2
  rect 0.914x1.219 smd: A(1.638,0) C(-1.638,0)
SOT23
  rect 1.016x1.397 smd: 1(-0.94,-1.118) 2(0.94,-1.118) 3(0,1.118)
SOT23_B
  rect 0.61x1.041 smd: 1(-0.958,-1.15) 2(0.958,-1.15) 3(0,1.15)
SSOP20-4
  rect 0.33x1.778 smd: 1(-2.925,-3.555) 2(-2.275,-3.555) 3(-1.625,-3.555) 4(-0.975,-3.555) 5(-0.325,-3.555) 6(0.325,-3.555) 7(0.975,-3.555) 8(1.625,-3.555) 9(2.275,-3.555) 10(2.925,-3.555) 11(2.925,3.555) 12(2.275,3.555) 13(1.625,3.555) 14(0.975,3.555) 15(0.325,3.555) 16(-0.325,3.555) 17(-0.975,3.555) 18(-1.625,3.555) 19(-2.275,3.555) 20(-2.925,3.555)
TSML394W319H235
  rect 1.6x1.702 smd: 1(-3.01,-5.397) 2(-1.003,-5.397) 3(1.003,-5.397) 4(3.01,-5.397) 5(3.01,5.397) 6(1.003,5.397) 7(-1.003,5.397) 8(-3.01,5.397)
unnamed#2
  round 3.937 hole 2.667 unplated: (0,0)

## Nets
+3.3V_AUX: C56.1(N1) P1.D32(N32) R37.2(N2)
+3.3V_SDP: P1.C39(N39) P1.D36(N36) P1.D38(N38) P1.D40(N40) P4.1(N1) R38.1(N1) UNK+3.3V.1
+12V_SDP: P1.C35(N35) P1.C37(N37) R33.2(N2) UNK+12V.1
AGND: A1.2(DGND) A1.9(REF) A2.2(DGND) A2.9(REF) AGND1.1(N1) AGND2.1(N1) AGND3.1(N1) AGND4.1(N1) C2.2(N2) C3.2(N2) C6.2(N2) C7.2(N2) C8.2(N2) C9.2(N2) C10.1(N1) C12.1(N1) C13.2(N2) C14.2(N2) C16.2(N2) C17.2(N2) C18.2(N2) C19.2(N2) C20.2(N2) C21.2(N2) C22.2(N2) C23.2(N2) C24.2(N2) C25.2(N2) C26.2(N2) C27.2(N2) C30.2(N2) C31.2(N2) C33.2(N2) C34.2(N2) C35.2(N2) C36.2(N2) C37.2(N2) C38.2(N2) C40.2(N2) C41.2(N2) C43.2(N2) C44.2(N2) C46.2(N2) C47.2(N2) C49.2(N2) C50.2(N2) C52.2(N2) C53.2(N2) C54.2(N2) C55.2(N2) C57.2(N2) C58.2(N2) C59.2(N2) C60.2(N2) C63.2(N2) C64.2(N2) C67.2(N2) CR1.1(P) CR2.1(P) D6.1(N1) D7.2(N2) D8.1(N1) D9.2(N2) DS1.C(N) J1.2(SH1) J1.3(SH2) J1.4(SH3) J1.5(SH4) J2.2(SH1) J2.3(SH2) J2.4(SH3) J2.5(SH4) J3.2(SH1) J3.3(SH2) J3.4(SH3) J3.5(SH4) J4.2(SH1) J4.3(SH2) J4.4(SH3) J4.5(SH4) JP1.3(B) R4.2(N2) R6.2(N2) R12.1(N1) R14.2(N2) R24.2(N2) RN3.4(N1) RN4.4(N1) T1.6(SECP1) T1.7(SECN2) U1.4(ADCN) U1.5(GND_1) U1.6(GND_2) U1.7(GND_3) U1.9(GND_4) U1.18(GND_5) U1.22(GND_6) U2.4(ADCN) U2.5(GND_1) U2.6(GND_2) U2.7(GND_3) U2.9(GND_4) U2.18(GND_5) U2.22(GND_6) U3.5(GND) U5.4(GND) U6.11(GND2_1) U6.19(GND2_2) U7.11(GND2_1) U7.19(GND2_2) U11.3(GND) U11.PAD U13.3(GND) U13.PAD U14.3(GND) U14.PAD U17.5(GND)
DGND: C1.2(N2) C4.2(N2) C11.2(N2) C28.2(N2) C29.1(N1) C39.2(N2) C42.2(N2) C45.2(N2) C48.2(N2) C51.2(N2) C56.2(N2) C61.2(N2) C62.2(N2) C67.1(N1) DGND1.1(N1) DGND2.1(N1) DS2.C(N) P1.C1(N1) P1.C4(N4) P1.C5(N5) P1.C8(N8) P1.C9(N9) P1.C12(N12) P1.C13(N13) P1.C16(N16) P1.C17(N17) P1.C20(N20) P1.C21(N21) P1.C24(N24) P1.C25(N25) P1.C28(N28) P1.C29(N29) P1.C32(N32) P1.C33(N33) P1.C36(N36) P1.C38(N38) P1.C40(N40) P1.D2(N2) P1.D3(N3) P1.D6(N6) P1.D7(N7) P1.D10(N10) P1.D13(N13) P1.D16(N16) P1.D19(N19) P1.D22(N22) P1.D25(N25) P1.D28(N28) P1.D37(N37) P1.D39(N39) P1.G1(N1) P1.G4(N4) P1.G5(N5) P1.G8(N8) P1.G11(N11) P1.G14(N14) P1.G17(N17) P1.G20(N20) P1.G23(N23) P1.G26(N26) P1.G29(N29) P1.G32(N32) P1.G35(N35) P1.G38(N38) P1.G40(N40) P1.H2(N2) P1.H3(N3) P1.H6(N6) P1.H9(N9) P1.H12(N12) P1.H15(N15) P1.H18(N18) P1.H21(N21) P1.H24(N24) P1.H27(N27) P1.H30(N30) P1.H33(N33) P1.H36(N36) P1.H39(N39) R30.1(N1) R31.1(N1) R39.1(N1) R40.2(N2) R43.1(N1) R44.2(N2) U4.4(GND1) U4.5(GND2) U4.PAD U6.2(GND1_1) U6.10(GND1_2) U7.2(GND1_1) U7.10(GND1_2) U19.3(E2) U19.4(VSS) U19.7(WC_N)
VDD: C21.1(N1) C30.1(N1) C31.1(N1) C46.1(N1) C47.1(N1) R25.2(N2) R53.1(N1) R54.1(N1) U1.19(PD_LDO_N) U1.20(VDD) U2.19(PD_LDO_N) U2.20(VDD) VDD.1(N1)
VDD1: C11.1(N1) R29.2(N2) U7.1(VDD1) VDD1.1(N1)
VDD2: C7.1(N1) C12.2(N2) U6.18(VDD2) U7.20(VDD2) VDD2.1(N1)
VDDA: C1.1(N1) C4.1(N1) R35.2(N2) T1.2(PRIP1) T1.3(PRIN2) U6.9(VDDA) VDDA.1(N1)
+ISO: C13.1(N1) R5.1(N1) R7.2(N2) R20.1(N1) U6.20(VREG) U11.4(EN) U11.6(VIN) UNK+ISO.1
+VS: A1.8(+VS) A2.8(+VS) C16.1(N1) C35.1(N1) C36.1(N1) C52.1(N1) C53.1(N1) R17.2(N2) R21.1(N1) UNK+VS.1
-ISO: R8.2(N2) R11.1(N1) UNK-ISO.1
-VS: A1.3(-VS) A1.6(WR_N) A2.3(-VS) A2.6(WR_N) C18.1(N1) C37.1(N1) C38.1(N1) C54.1(N1) C55.1(N1) R19.2(N2) R22.1(N1) UNK-VS.1
AMP_OUTA: AMP_A.1(N1) C65.2(N2) CR1.3(C) RN1.7(N2) RN1.8(N2) U1.3(AMP_OUT)
AMP_OUTB: AMP_B.1(N1) C66.2(N2) CR2.3(C) RN2.7(N2) RN2.8(N2) U2.3(AMP_OUT)
CA+: CA+.1(N1) D6.2(N2) J1.1(CNTR) P2.3(N3) R47.1(N1)
CA-: CA-.1(N1) D7.1(N1) J2.1(CNTR) P3.1(N1) R48.1(N1)
CB+: CB+.1(N1) J3.1(CNTR) P2.1(N1)
CB-: CB-.1(N1) J4.1(CNTR) P3.3(N3)
CNV: CNV.1(N1) U1.13(CNV) U2.13(CNV) U7.15(SSS_N)
DCLK: DCLK.1(N1) P1.H29(N29) U7.9(DCLK)
G0A_ISO: A1.4(A0) ADR0_A.1(N1) U6.15(VOB)
G0B_ISO: A2.4(A0) ADR0_B.1(N1) U6.13(VOD)
G1A_ISO: A1.5(A1) ADR1_A.1(N1) U6.16(VOA)
G1B_ISO: A2.5(A1) ADR1_B.1(N1) U6.14(VOC)
GA0: P1.C34(N34) U19.1(E0)
GA1: P1.D35(N35) U19.2(E1)
GAIN_0A: R44.1(N1) R46.1(N1) U6.6(VIB)
GAIN_0B: R40.1(N1) R42.1(N1) U6.8(VID)
GAIN_1A: R43.2(N2) R45.1(N1) U6.5(VIA)
GAIN_1B: R39.2(N2) R41.1(N1) U6.7(VIC)
IN_A: IN_A.1(N1) R51.2(N2) RN1.5(N2)
IN_B: IN_B.1(N1) R52.2(N2) RN2.5(N2)
MCLK: MCLK.1(N1) P1.H35(N35) U7.3(MCLK)
MISO: MISO.1(N1) P1.H32(N32) U7.5(MI)
MOSI: MOSI.1(N1) P1.H34(N34) U7.4(MO)
MSS: MSS.1(N1) P1.H31(N31) U7.6(MSS_N)
REF_OUTA: CR1.2(N) U1.24(REF_OUT)
REF_OUTB: CR2.2(N) U2.24(REF_OUT)
SCK: SCK.1(N1) U1.15(SCK) U2.15(SCK) U7.18(SCLK)
SDI_A: JP1.1(A) SDIA.1(N1) U7.17(SI)
SDO_A: JP2.1(A) SDOA.1(N1) U1.14(SDO)
SDO_B: SDOB.1(N1) U2.14(SDO) U7.16(SO)
UNNAMED_2_ADR45XX_I73_NC4: R2.1(N1) U5.7(NC4)
UNNAMED_2_ADR45XX_I73_VIN: C2.1(N1) C3.1(N1) R1.2(N2) U5.2(VIN)
UNNAMED_2_ADR45XX_I73_VOUT: C5.1(N1) R3.1(N1) U5.6(VOUT)
UNNAMED_2_ADUM3470_I1_FB: R5.2(N2) R6.1(N1) U6.17(FB)
UNNAMED_2_ADUM3470_I1_OC: R4.1(N1) U6.12(OC)
UNNAMED_2_ADUM3470_I1_X1: R56.1(N1) T1.4(PRIP2) U6.1(X1)
UNNAMED_2_ADUM3470_I1_X2: R55.1(N1) T1.1(PRIN1) U6.4(X2)
UNNAMED_2_CAP_I27_N1: C9.1(N1) L1.2(N2) R7.1(N1)
UNNAMED_2_CAP_I34_N2: C10.2(N2) L2.2(N2) R8.1(N1)
UNNAMED_2_CAP_I84_N2: C5.2(N2) R2.2(N2)
UNNAMED_2_CAP_I98_N1: C61.1(N1) R55.2(N2)
UNNAMED_2_CAP_I100_N1: C62.1(N1) R56.2(N2)
UNNAMED_2_DIOSCHOTTKY_I28_N: D1.C(N) D3.C(N) L1.1(N1)
UNNAMED_2_DIOSCHOTTKY_I28_P: D1.A(P) D2.C(N) T1.8(SECP2)
UNNAMED_2_DIOSCHOTTKY_I29_P: D2.A(P) D4.A(P) L2.1(N1)
UNNAMED_2_DIOSCHOTTKY_I30_P: D3.A(P) D4.C(N) T1.5(SECN1)
UNNAMED_2_RES_I92_N2: R9.2(N2) RN3.8(N2)
UNNAMED_2_RES_I96_N2: R10.2(N2) RN4.8(N2)
UNNAMED_2_RESNET8P4R_I87_N1: RN3.1(N1) RN3.2(N1) RN3.3(N1)
UNNAMED_2_RESNET8P4R_I93_N1: RN4.1(N1) RN4.2(N1) RN4.3(N1)
UNNAMED_3_ADP1614_I77_CLRES: C39.1(N1) R34.2(N2) U4.8(VIN) U4.9(CLRES/FREQ)
UNNAMED_3_ADP1614_I77_COMP: C29.2(N2) C32.1(N1) U4.1(COMP)
UNNAMED_3_ADP1614_I77_EN: C28.1(N1) L3.1(N1) R28.2(N2) R34.1(N1) U4.3(EN)
UNNAMED_3_ADP1614_I77_FB: R31.2(N2) R32.1(N1) U4.2(FB)
UNNAMED_3_ADP1614_I77_SS: C42.1(N1) U4.10(SS)
UNNAMED_3_ADP1614_I77_SW1: D5.A(P) L3.2(N2) U4.6(SW1) U4.7(SW2)
UNNAMED_3_ADP7118_I9_EN: C17.1(N1) R18.2(N2) U14.4(EN) U14.6(VIN)
UNNAMED_3_ADP7118_I9_SENSE: R25.1(N1) U14.1(VOUT) U14.2(SENSE/ADJ)
UNNAMED_3_ADP7118_I18_EN: C19.1(N1) R21.2(N2) U13.4(EN) U13.6(VIN)
UNNAMED_3_ADP7118_I18_SENSE: R23.1(N1) R24.1(N1) U13.2(SENSE/ADJ)
UNNAMED_3_ADP7118_I18_VOUT: R23.2(N2) R26.1(N1) U13.1(VOUT)
UNNAMED_3_ADP7118_I24_SENSE: R13.1(N1) R14.1(N1) U11.2(SENSE/ADJ)
UNNAMED_3_ADP7118_I24_VOUT: R13.2(N2) R17.1(N1) U11.1(VOUT)
UNNAMED_3_ADP7182V5_I43_ADJ: R12.2(N2) R15.1(N1) R16.1(N1) U3.2(ADJ)
UNNAMED_3_ADP7182V5_I43_EN: C14.1(N1) R11.2(N2) U3.3(EN) U3.6(VIN) U3.PAD(EPAD)
UNNAMED_3_ADP7182V5_I43_VOUT: C15.2(N2) R16.2(N2) R19.1(N1) U3.1(VOUT)
UNNAMED_3_ADP7182V6_I29_EN: C20.1(N1) R22.2(N2) U17.3(EN) U17.6(VIN) U17.PAD(EPAD)
UNNAMED_3_ADP7182V6_I29_VOUT: C22.1(N1) R27.1(N1) U17.1(VOUT)
UNNAMED_3_CAP_I82_N1: C48.1(N1) C51.1(N1) L4.2(N2) R32.2(N2) R35.1(N1)
UNNAMED_3_CAP_I86_N2: C32.2(N2) R30.2(N2)
UNNAMED_3_CAP_I96_N1: C45.1(N1) D5.C(N) L4.1(N1)
UNNAMED_3_CAP_I98_N1: C15.1(N1) R15.2(N2)
UNNAMED_3_CN2P_I157_N2: P4.2(N2) R28.1(N1) R29.1(N1)
UNNAMED_3_DIOLED_I122_P: DS2.A(P) R33.1(N1)
UNNAMED_3_DIOLED_I125_P: DS1.A(P) R20.2(N2)
UNNAMED_4_CN160PCDGH_I2_N30: P1.C30(N30) U19.6(SCL)
UNNAMED_4_CN160PCDGH_I2_N31: P1.C31(N31) U19.5(SDA)
UNNAMED_4_CN160PCDGH_I3_N1: P1.D1(N1) R38.2(N2)
UNNAMED_4_CN160PCDGH_I3_N30: P1.D30(N30) P1.D31(N31)
UNNAMED_4_CN160PCDGH_I4_N9: P1.G9(N9) R41.2(N2)
UNNAMED_4_CN160PCDGH_I4_N10: P1.G10(N10) R42.2(N2)
UNNAMED_4_CN160PCDGH_I5_N7: P1.H7(N7) R45.2(N2)
UNNAMED_4_CN160PCDGH_I5_N8: P1.H8(N8) R46.2(N2)
UNNAMED_4_ICM24CXX_I6_VCC: R37.1(N1) U19.8(VCC)
UNNAMED_5_AD8251_I6_: A1.10(+IN) C57.1(N1) R47.2(N2)
UNNAMED_5_AD8251_I6__1: A1.1(-IN) C58.1(N1) R48.2(N2)
UNNAMED_5_AD8251_I6_OUT: A1.7(OUT) R51.1(N1)
UNNAMED_5_AD8251_I180_: A2.1(-IN) C60.1(N1) R50.2(N2)
UNNAMED_5_AD8251_I180__1: A2.10(+IN) C59.1(N1) R49.2(N2)
UNNAMED_5_AD8251_I180_OUT: A2.7(OUT) R52.1(N1)
UNNAMED_5_ADAQ798X_I1_IN: C65.1(N1) RN1.1(N1) RN1.2(N1) RN1.6(N2) U1.2(IN-)
UNNAMED_5_ADAQ798X_I1_SDI: JP1.2(COM) U1.16(SDI)
UNNAMED_5_ADAQ798X_I184_IN: C66.1(N1) RN2.1(N1) RN2.2(N1) RN2.6(N2) U2.2(IN-)
UNNAMED_5_ADAQ798X_I184_SDI: JP2.2(COM) U2.16(SDI)
UNNAMED_5_CN3P_I304_N2: D8.2(N2) P2.2(N2) R49.1(N1)
UNNAMED_5_CN3P_I305_N2: D9.1(N1) P3.2(N2) R50.1(N1)
UNNAMED_5_RESNET8P4R_I216_N1: RN1.3(N1) RN1.4(N1)
UNNAMED_5_RESNET8P4R_I220_N1: RN2.3(N1) RN2.4(N1)
V+: C23.1(N1) C24.1(N1) C25.1(N1) C40.1(N1) C41.1(N1) R1.1(N1) R18.1(N1) R26.2(N2) U1.10(PD_REF_N) U1.11(PD_AMP_N) U1.21(V+) U2.10(PD_REF_N) U2.11(PD_AMP_N) U2.21(V+) V+.1(N1)
V-: C26.1(N1) C27.1(N1) C43.1(N1) C44.1(N1) R27.2(N2) U1.8(V-) U2.8(V-) V-.1(N1)
VBIAS_A: C63.1(N1) RN3.5(N2) RN3.6(N2) RN3.7(N2) U1.1(IN+) VB_A.1(N1)
VBIAS_B: C64.1(N1) RN4.5(N2) RN4.6(N2) RN4.7(N2) U2.1(IN+) VB_B.1(N1)
VIO: C33.1(N1) C34.1(N1) C49.1(N1) C50.1(N1) JP2.3(B) R53.2(N2) R54.2(N2) U1.17(VIO) U2.17(VIO) VIO.1(N1)
VREF: C6.1(N1) C8.1(N1) R3.2(N2) R9.1(N1) R10.1(N1) U1.23(REF) U2.23(REF) VREF.1(N1)

Pads without a net: D6 3; D7 3; D8 3; D9 3; P1 C2 C3 C6 C7 C10 C11 C14 C15 C18 C19 C22 C23 C26 C27 D4 D5 D8 D9 D11 D12 D14 D15 D17 D18 D20 D21 D23 D24 D26 D27 D29 D33 D34 G2 G3 G6 G7 G12 G13 G15 G16 G18 G19 G21 G22 G24 G25 G27 G28 G30 G31 G33 G34 G36 G37 G39 H1 H4 H5 H10 H11 H13 H14 H16 H17 H19 H20 H22 H23 H25 H26 H28 H37 H38 H40; U1 12; U2 12; U3 4; U5 1 3 5 8; U6 3; U7 7 8 12 13 14; U11 5; U13 5; U14 5; U17 2 4

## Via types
v1: diameter 0.508, hole 0.254, TOP to BOTTOM, 516 vias
v2: diameter 1.016, hole 0.508, TOP to BOTTOM, 8 vias
v3: diameter 0.66, hole 0.406, TOP to BOTTOM, 64 vias

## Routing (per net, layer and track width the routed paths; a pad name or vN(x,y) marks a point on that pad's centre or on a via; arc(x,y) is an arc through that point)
+3.3V_AUX: length 29.3
  TOP w0.5: v1(75.12,19.88) 73.25,18 70.75,18 67.25,14.5 67.25,12 66.25,11 59,11 56,8 C56.1 R37.2
  BOTTOM w0.5: P1.D32 75.14,19.89 v1(75.12,19.88)
+3.3V_SDP: length 12.3
  TOP w0.75: R38.1 v1(80.75,13.62)
  LAYER3 w0.2: UNK+3.3V.1 63.81,16 ; UNK+3.3V.1 61.69,16 ; UNK+3.3V.1 62.75,17.06 ; UNK+3.3V.1 62.75,14.94 ; 57.69,14.38 P4.1 ; P4.1 58.75,13.31 ; P4.1 58.75,15.44 ; P4.1 59.81,14.38
  BOTTOM w0.5: v1(75.12,9.75) 75.14,9.73 P1.D40 ; 75.91,12.28 75.15,12.28 v1(75.12,12.25) ; v1(77.88,11) 77.87,11.01 P1.C39 ; v1(75.12,14.75) 75.19,14.81 P1.D36
+12V_SDP: length 32.4
  TOP w0.5: v1(78.38,13.5) 79,12.88 79,5.8 78.7,5.5 70,5.5 66.75,2.25 UNK+12V.1 62.54,2.25 62.04,2.75 R33.2
  BOTTOM w0.2: 78.3,13.54 78.62,13.88 78.62,15.5 78.04,16.09 P1.C35
  BOTTOM w0.5: 77.17,13.54 78.33,13.54 v1(78.38,13.5)
AGND: length 324.4
  TOP w0.2: U1.5 26.06,12.75 ; U1.5 25.05,12.75 ; U1.5 25.55,12.32 ; AGND1.1 34.31,4.38 ; AGND1.1 33.25,3.31 ; AGND1.1 32.19,4.38 ; AGND1.1 33.25,5.44 ; 20.45,20.57 RN3.4 18.85,20.57 ; 27,18.32 C40.2 ; C40.2 26.3,19 ; C40.2 27.7,19 ; J3.2 5.52,50.87 ; J3.2 2.68,49.3 ; J3.2 2.68,52.44 ; J2.2 2.68,5.07 ; J2.2 2.68,1.92 ; J2.2 5.52,3.5 ; D7.2 10.35,7.15 ; D7.2 9.53,6.54 ; D7.2 10.35,5.94 ; D7.2 11.17,6.54 ; C58.2 11.43,12 ; C58.2 10.75,12.7 ; C58.2 10.07,12 ; C58.2 10.75,11.3 ; 28.05,19 C46.2 ; C46.2 29.45,19 ; C46.2 28.75,18.32 ; 9.28,23.46 D6.1 ; D6.1 10.1,24.06 ; D6.1 10.1,22.85 ; D6.1 10.92,23.46 ; J4.4 5.52,45.63 ; J4.4 2.68,44.06 ; J4.4 2.68,47.2 ; 25.05,40.75 U2.5 ; U2.5 26.06,40.75 ; U2.5 25.55,40.32 ; 12.3,50.4 C8.2 ; C8.2 13.25,51.5 ; C8.2 12.3,52.6 ; 31.55,16.5 C49.2 ; C49.2 32.95,16.5 ; C49.2 32.25,15.82 ; 45.8,64.57 DS1.C ; DS1.C 45.02,65.25 ; DS1.C 45.8,65.93 ; 10.32,17.25 C57.2 ; C57.2 11,17.95 ; C57.2 11.68,17.25 ; AGND2.1 20.75,29.56 ; AGND2.1 19.69,28.5 ; AGND2.1 20.75,27.44 ; AGND2.1 21.81,28.5 ; C50.2 32.95,44.5 ; C50.2 32.25,43.82 ; C50.2 31.55,44.5 ; AGND4.1 14.06,62 ; AGND4.1 13,63.06 ; AGND4.1 13,60.94 ; AGND4.1 11.94,62 ; 28.07,9.75 C43.2 ; C43.2 28.75,9.05 ; C43.2 28.75,10.45 ; 14.87,10.24 A1.2 14.87,12.17 ; 2.68,57.81 J3.4 ; J3.4 5.52,59.38 ; J3.4 2.68,60.95 ; C52.2 16.08,19.12 ; C52.2 14.67,19.12 ; C52.2 15.38,18.45 ; 26.25,39.55 U2.6 ; U2.6 26.25,40.56 ; U2.6 25.82,40.05 ; 19.69,4 AGND3.1 ; AGND3.1 20.75,2.94 ; AGND3.1 21.81,4 ; AGND3.1 20.75,5.06 ; C41.2 27.7,47 ; C41.2 27,46.32 ; C41.2 26.3,47 ; C44.2 28.75,38.45 ; C44.2 28.07,37.75 ; C44.2 28.75,37.05 ; 2.68,35.55 J4.2 ; J4.2 5.52,37.12 ; J4.2 2.68,38.69 ; 28.05,47 C47.2 ; C47.2 29.45,47 ; C47.2 28.75,46.32 ; C60.2 11.68,39.25 ; C60.2 11,38.55 ; C60.2 11,39.95 ; C59.2 11,44.45 ; C59.2 11.68,43.75 ; C59.2 11,43.05 ; 10.1,33.19 D9.2 ; D9.2 9.28,33.79 ; D9.2 10.92,33.79 ; D9.2 10.1,34.4 ; U1.18 29.68,15.45 ; U1.18 29.25,15.95 ; U1.18 29.25,14.94 ; 2.68,24.18 J1.4 ; J1.4 2.68,27.33 ; J1.4 5.52,25.75 ; 23.42,17.63 C63.2 24.58,17.63 ; C53.2 16.2,47.25 ; C53.2 15.5,46.57 ; C53.2 14.8,47.25 ; 25.82,12.05 U1.6 ; U1.6 26.25,11.55 ; U1.6 26.25,12.56 ; 12.25,53.05 C6.2 ; C6.2 12.93,53.75 ; C6.2 12.25,54.45 ; 25.05,13.25 U1.4 26.06,13.25 ; 14.67,7.62 C54.2 ; C54.2 15.38,8.3 ; C54.2 16.08,7.62 ; 2.68,15.67 J1.2 ; J1.2 2.68,18.82 ; J1.2 5.52,17.25 ; U2.7 26.75,40.62 ; 24.46,46.13 C64.2 23.29,46.13 ; v1(27.25,14.38) 27.25,15 ; J2.4 5.52,12 ; J2.4 2.68,10.43 ; J2.4 2.68,13.58 ; 27.75,39.25 27.75,39.8 ; 10.1,48.6 D8.1 ; D8.1 10.92,49.21 ; D8.1 10.1,49.81 ; 16.2,35.75 C55.2 15.5,36.43 ; 19.52,47.67 RN4.4 20.32,48.32
  TOP w0.25: 27.25,15.7 U1.22 27.25,15 ; v1(49.12,34.62) 48.75,34.25 ; A1.9 14.87,14.38 14.88,14.38 ; 29.25,43.7 U2.18 29.25,42.45 v1(28.75,42.45) ; A2.2 v1(15,40.37) ; v1(27.25,42.5) U2.22 27.25,43.7 ; v1(14.9,42.45) 15,42.55 A2.9 ; 24.6,40.75 24.55,40.75 24.55,41.25 U2.4 ; 26.25,39.1 26.25,39.05 26.75,39.05 U2.7 ; 26.75,12.62 U1.7 26.75,11.8 ; 27.75,39.8 U2.9 27.75,40.64 27.85,40.64 27.85,41.12 v1(27.25,41.12) ; 27.75,12.62 U1.9 27.75,11.8
  TOP w0.37: U6.11 47.97,48.17 47.75,48.4 v1(47.75,48.88)
  TOP w0.4: 48.75,38 C67.2 50.29,38 ; C57.2 v1(11,16.38) ; C64.2 23.88,46.75 v1(23.75,46.88) ; C63.2 v1(24,18.25)
  TOP w0.5: C55.2 v1(15.5,35.1) ; C40.2 v1(27,19.76) ; U5.4 v1(22.76,58.16) ; RN3.4 19.65,19.77 v1(19.62,19.75) ; C16.2 v1(32.98,65.75) ; C47.2 v1(28.75,47.76) ; C10.1 v1(39.5,56.48) ; C2.2 v1(23.75,57.76) ; C6.2 v1(11.49,53.75) ; RN4.4 18.65,48.32 ; DS1.C v1(46.66,65.25) ; C52.2 v1(15.38,19.88) ; C60.2 v1(10.24,39.25) ; C50.2 32.25,45 v1(32,45.25) ; JP1.3 v1(37.05,15.17) ; C53.2 v1(15.5,48.01) ; C49.2 v1(32.25,17.26) ; C8.2 v1(11.27,51.5) ; T1.6 v1(45.62,57.5) ; C9.2 v1(39.5,56.52) ; C12.1 v1(45.72,28.88) ; R14.2 v1(34.42,61.25) ; C46.2 v1(28.75,19.76) ; C54.2 v1(15.38,6.87) ; D8.1 v1(9.2,49.21) ; v1(26.4,47.75) 27,47.15 C41.2 ; C17.2 v1(34.75,53.49) ; C43.2 v1(29.51,9.75) ; C44.2 v1(29.51,37.75) ; T1.7 v1(45.62,55.5) ; C59.2 v1(10.24,43.75) ; C21.2 v1(34.75,53.26) ; C13.2 v1(33.02,65.75)
  LAYER2 w0.2: 33.25,3.31 AGND1.1 ; AGND1.1 32.19,4.38 ; AGND1.1 33.25,5.44 ; AGND1.1 34.31,4.38 ; 19.69,28.5 AGND2.1 ; AGND2.1 21.81,28.5 ; AGND2.1 20.75,27.44 ; AGND2.1 20.75,29.56 ; 20.75,2.94 AGND3.1 ; AGND3.1 20.75,5.06 ; AGND3.1 21.81,4 ; AGND3.1 19.69,4 ; AGND4.1 13,63.06 ; AGND4.1 13,60.94 ; AGND4.1 14.06,62 ; AGND4.1 11.94,62
  LAYER3 w0.2: AGND1.1 33.25,5.44 ; AGND1.1 33.25,3.31 ; AGND1.1 32.19,4.38 ; AGND1.1 34.31,4.38 ; AGND4.1 14.06,62 ; AGND4.1 11.94,62 ; AGND4.1 13,60.94 ; AGND4.1 13,63.06 ; 19.69,28.5 AGND2.1 ; AGND2.1 20.75,27.44 ; AGND2.1 20.75,29.56 ; AGND2.1 21.81,28.5 ; AGND3.1 20.75,5.06 ; AGND3.1 19.69,4 ; AGND3.1 20.75,2.94 ; AGND3.1 21.81,4
  BOTTOM w0.2: 2.68,57.81 J3.4 ; J3.4 5.52,59.38 ; J3.4 2.68,60.95 ; J1.4 2.68,27.33 ; J1.4 2.68,24.18 ; J1.4 5.52,25.75 ; 28.13,43.12 C31.2 29.37,43.12 ; 16.12,39.88 C38.2 14.88,39.88 ; 47.55,49 R4.2 ; R4.2 48.25,48.32 ; R4.2 48.25,49.68 ; 14.88,42.87 C36.2 16.12,42.87 ; 30.25,17.04 C33.2 29.63,16.39 ; AGND2.1 21.81,28.5 ; AGND2.1 19.69,28.5 ; AGND2.1 20.75,29.56 ; AGND2.1 20.75,27.44 ; 46.3,42.5 R6.2 ; R6.2 47,43.18 ; R6.2 47.7,42.5 ; R6.2 47,41.82 ; J4.4 2.68,47.2 ; J4.4 2.68,44.06 ; J4.4 5.52,45.63 ; 21.63,42.87 CR2.1 ; CR2.1 22.44,41.87 ; CR2.1 23.24,42.87 ; AGND1.1 34.31,4.38 ; AGND1.1 32.19,4.38 ; AGND1.1 33.25,3.31 ; AGND1.1 33.25,5.44 ; AGND4.1 14.06,62 ; AGND4.1 11.94,62 ; AGND4.1 13,63.06 ; AGND4.1 13,60.94 ; 15.99,11.76 C37.2 14.76,11.76 ; 29.37,15.12 C30.2 28.13,15.12 ; 2.68,10.43 J2.4 ; J2.4 2.68,13.58 ; J2.4 5.52,12 ; 27.87,40.38 C27.2 26.63,40.38 ; J4.2 5.52,37.12 ; J4.2 2.68,35.55 ; J4.2 2.68,38.69 ; 14.76,14.74 C35.2 15.99,14.74 ; J3.2 2.68,52.44 ; J3.2 2.68,49.3 ; J3.2 5.52,50.87 ; 26.63,15.12 C24.2 27.87,15.12 ; J1.2 5.52,17.25 ; J1.2 2.68,15.67 ; J1.2 2.68,18.82 ; CR1.1 22.24,14.99 ; CR1.1 20.63,14.99 ; CR1.1 21.44,15.99 ; CR1.1 21.44,13.99 ; 29.63,44.38 C34.2 30.25,45.04 ; 27.87,43.12 C25.2 26.63,43.12 ; 26.63,12.38 C26.2 27.87,12.38 ; 2.68,1.92 J2.2 ; J2.2 5.52,3.5 ; J2.2 2.68,5.07 ; AGND3.1 21.81,4 ; AGND3.1 19.69,4 ; AGND3.1 20.75,5.06 ; AGND3.1 20.75,2.94
  BOTTOM w0.25: U17.5 v1(35,29.14)
  BOTTOM w0.3: U3.5 39.38,45.75
  BOTTOM w0.37: R4.2 48.12,48.88 v1(47.75,48.88)
  BOTTOM w0.4: CR2.1 22.44,44.06 v1(22.38,44.12) ; v1(30.88,44.38) 30.87,44.38 C34.2
  BOTTOM w0.5: C31.2 v1(28.75,42.45) ; C33.2 v1(30.95,16.39) ; C27.2 v1(27.25,41.12) ; R24.2 v1(25.25,58.92) ; C26.2 v1(27.25,13.12) ; C19.2 v1(29.5,58.27) ; C30.2 v1(28.75,14.38) ; C20.2 v1(33.27,30.25) ; C25.2 v1(27.25,42.5) ; C22.2 v1(37,28.51) ; C35.2 v1(15.38,14) ; C23.2 v1(29.5,58.23) ; C37.2 v1(15.38,12.5) ; C38.2 v1(15.5,40.62) ; C36.2 v1(15.5,42.13) ; C24.2 v1(27.25,14.38) ; C18.2 v1(39.88,43.45)
  vias: v1(2.8,37.23) v1(2.8,25.61) v1(7.25,56.75) v1(7.3,65.61) v1(7.3,63.11) v1(7.3,60.61) v1(7.3,58.11) v1(7.3,28.11) v1(7.3,15.61) v1(9,23.5) v1(9.5,12) v1(9.8,65.61) v1(9.8,63.11) v1(9.8,60.61) v1(9.8,58.11) v1(9.8,55.61) v1(9.8,53.11) v1(9.8,50.61) v1(9.8,45.61) v1(9.8,40.61) v1(9.8,33.11) v1(9.8,30.61) v1(9.8,28.11) v1(9.8,25.61) v1(9.8,20.61) v1(9.8,15.61) v1(9.8,10.61) v1(9.8,5.61) v1(9.8,3.11) v1(10.62,38.38) v1(10.75,13.25) v1(12.25,42.5) v1(12.25,20.5) v1(12.3,65.61) v1(12.3,63.11) v1(12.3,60.61) v1(12.3,58.11) v1(12.3,55.61) v1(12.3,53.11) v1(12.3,50.61) v1(12.3,40.61) v1(12.3,33.11) v1(12.3,30.61) v1(12.3,28.11) v1(12.3,25.61) v1(12.3,13.11) v1(12.3,5.61) v1(12.3,3.11) v1(12.75,23.5) v1(14.8,65.61) v1(14.8,63.11) v1(14.8,60.61) v1(14.8,48.11) v1(14.8,30.61) v1(14.8,28.11) v1(14.8,25.61) v1(14.8,23.11) v1(14.8,20.61) v1(14.8,13.11) v1(14.8,8.11) v1(14.8,5.61) v1(14.8,3.11) v1(17.3,65.61) v1(17.3,63.11) v1(17.3,60.61) v1(17.3,53.11) v1(17.3,48.11) v1(17.3,45.61) v1(17.3,40.61) v1(17.3,30.61) v1(17.3,28.11) v1(17.3,25.61) v1(17.3,23.11) v1(17.3,20.61) v1(17.3,18.11) v1(17.3,13.11) v1(17.3,10.61) v1(17.3,5.61) v1(17.3,3.11) v1(19.8,65.61) v1(19.8,63.11) v1(19.8,60.61) v1(19.8,58.11) v1(19.8,48.11) v1(19.8,45.61) v1(19.8,30.61) v1(19.75,27.12) v1(19.8,25.61) v1(19.8,20.61) v1(19.8,18.11) v1(19.8,5.61) v1(19.8,3.11) v1(22.12,27.38) v1(22.3,65.61) v1(22.3,63.11) v1(22.3,60.61) v1(22.3,48.11) v1(22.3,30.61) v1(22.3,25.61) v1(22.3,10.61) v1(22.3,5.61) v1(22.3,3.11) v1(24.8,65.61) v1(24.8,63.11) v1(24.8,60.61) v1(24.8,58.11) v1(24.8,53.11) v1(24.8,40.61) v1(24.8,38.11) v1(24.8,30.61) v1(24.8,28.11) v1(24.8,10.61) v1(24.8,5.61) v1(24.8,3.11) v1(27.3,58.11) v1(27.3,50.61) v1(27.3,30.61) v1(27.3,23.11) v1(27.3,20.61) v1(27.3,13.11) v1(27.3,5.61) v1(27.3,3.11) v1(29.8,48.11) v1(29.8,30.61) v1(29.8,23.11) v1(29.8,20.61) v1(29.8,10.61) v1(29.8,5.61) v1(29.8,3.11) v1(32.3,30.61) v1(32.3,28.11) v1(32.3,23.11) v1(32.3,20.61) v1(32.3,18.11) v1(32.3,10.61) v1(32.3,5.61) v1(32.3,3.11) v1(34.8,65.61) v1(34.8,63.11) v1(34.8,60.61) v1(34.8,38.11) v1(34.8,30.61) v1(34.8,23.11) v1(34.8,20.61) v1(34.8,18.11) v1(34.8,5.61) v1(34.8,3.11) v1(35,13.12) v1(35.12,10.62) v1(36.5,20.12) v1(36.62,23.12) v1(37.25,10.75) v1(37.3,60.61) v1(37.3,3.11) v1(39.8,58.11) v1(39.8,55.61) v1(39.75,12.62) v1(39.8,3.11) v1(39.88,20.25) v1(40,6.75) v1(40.5,32.75) v1(40.5,29.25) v1(40.5,26) v1(42.3,63.11) v1(42.3,50.61) v1(42.3,5.61) v1(42.3,3.11) v1(44.8,63.11) v1(44.8,50.61) v1(44.8,48.11) v1(44.8,15.61) v1(44.8,13.11) v1(44.8,10.61) v1(44.8,8.11) v1(44.8,3.11) v1(47.62,35.38) v1(47.62,34.62) v1(47.75,49.62) v1(48.38,35.38) v1(48.38,34.62) v1(48.5,49.62) v1(48.5,48.88) v1(49.12,35.38) v1(49.25,49.62) v1(49.25,48.88) v3(0.77,60.27) v3(0.77,58.49) v3(0.77,51.76) v3(0.77,49.98) v3(0.77,46.39) v3(0.77,44.74) v3(0.75,37.88) v3(0.75,36.25) v3(0.77,26.64) v3(0.77,24.87) v3(0.77,18.13) v3(0.77,16.36) v3(0.77,12.89) v3(0.77,11.12) v3(0.77,4.38) v3(0.77,2.61) v3(2.04,60.27) v3(2.04,58.49) v3(2.04,51.76) v3(2.04,49.98) v3(2.04,46.39) v3(2.04,44.74) v3(2,37.88) v3(2,36.25) v3(2.04,26.64) v3(2.04,24.87) v3(2.04,18.13) v3(2.04,16.36) v3(2.04,12.89) v3(2.04,11.12) v3(2.04,4.38) v3(2.04,2.61) v3(3.25,37.88) v3(3.25,36.25) v3(3.31,60.27) v3(3.31,58.49) v3(3.31,51.76) v3(3.31,49.98) v3(3.31,46.39) v3(3.31,44.74) v3(3.31,26.64) v3(3.31,24.87) v3(3.31,18.13) v3(3.31,16.36) v3(3.31,12.89) v3(3.31,11.12) v3(3.31,4.38) v3(3.31,2.61) v3(4.5,44.75) v3(4.5,37.88) v3(4.5,36.38) v3(4.5,2.62) v3(4.58,60.27) v3(4.58,58.49) v3(4.58,51.76) v3(4.58,49.98) v3(4.62,46.38) v3(4.58,26.64) v3(4.58,24.87) v3(4.58,18.13) v3(4.58,16.36) v3(4.58,12.89) v3(4.58,11.12) v3(4.58,4.38)
DGND: length 234.4
  TOP w0.2: 65,59.05 C62.2 ; C62.2 64.32,59.75 ; C62.2 65,60.45 ; U19.7 61.35,6.37 ; U19.7 59.96,6.97 ; U19.7 v1(58.49,6.37) ; U19.7 59.96,5.76 ; 63.65,7.63 U19.3 ; U19.3 65.04,8.24 ; U19.3 65.04,7.03 ; U19.3 v1(66.51,7.63) ; DS2.C 57.48,2.75 ; DS2.C v1(55.84,2.75) ; DS2.C 56.7,2.07 ; DS2.C 56.7,3.43 ; C1.2 65.2,56.6 ; C1.2 65.2,54.4 ; C1.2 64.25,55.5 ; 64.75,52.55 C61.2 ; C61.2 64.75,53.95 ; C61.2 64.07,53.25 ; U7.2 57.47,28.98 57.5,28.95 C11.2 ; 63.25,61.94 DGND1.1 ; DGND1.1 62.19,63 ; DGND1.1 64.31,63 ; DGND1.1 63.25,64.06 ; 63.65,8.9 U19.4 ; U19.4 65.04,8.3 ; U19.4 v1(66.51,8.9) ; 64.32,57.75 C4.2 65,57.05 ; 65.19,16 DGND2.1 ; DGND2.1 66.25,14.94 ; DGND2.1 66.25,17.06 ; DGND2.1 67.31,16 ; v1(55.5,34.88) 55.5,34.48 U7.10 ; 57.5,6.05 C56.2 ; C56.2 58.18,6.75 ; C56.2 56.82,6.75
  TOP w0.37: U6.10 55.81,48.7 55.75,48.75 v1(55.75,48.88) ; v1(57.25,43) 57.22,42.98 U6.2
  TOP w0.4: 56,38 C67.1 54.21,38
  TOP w0.5: R44.2 v1(65.08,50.5) ; R40.2 v1(65.08,48.25) ; R43.1 v1(65.08,51.5) ; C29.1 v1(65.58,34) ; C39.2 v1(65.51,32.38) ; C4.2 v1(65.76,57.75) ; C45.2 66.12,39.62 v1(66.88,38.88) ; C1.2 v1(66.23,55.5) ; C28.2 v1(65.73,30.25) ; C62.2 v1(65.76,59.75) ; C42.2 v1(65.01,33.34) ; C61.2 v1(65.51,53.25) ; R39.1 v1(65.08,49.25) ; C56.2 v1(57.5,7.53) ; C51.2 v1(66.98,44.38) ; R31.1 v1(69.25,38.62) ; C11.2 v1(58.28,28.5) ; C48.2 v1(66.98,42)
  LAYER2 w0.2: 65.19,16 DGND2.1 ; DGND2.1 67.31,16 ; DGND2.1 66.25,17.06 ; DGND2.1 66.25,14.94 ; 62.19,63 DGND1.1 ; DGND1.1 63.25,61.94 ; DGND1.1 64.31,63 ; DGND1.1 63.25,64.06
  LAYER3 w0.2: DGND1.1 63.25,64.06 ; DGND1.1 63.25,61.94 ; DGND1.1 62.19,63 ; DGND1.1 64.31,63
  BOTTOM w0.2: P1.H39 v1(70.13,11.01) ; P1.H39 71.44,11.01 ; P1.H39 70.83,10.39 ; P1.H39 70.83,11.62 ; P1.H6 v1(70.13,52.91) ; P1.H6 71.44,52.91 ; P1.H6 70.83,53.53 ; P1.H6 70.83,52.3 ; P1.H12 71.44,45.3 ; P1.H12 70.83,45.91 ; P1.H12 70.83,44.68 ; P1.H12 v1(70.13,45.3) ; P1.D22 v1(75.21,32.59) ; P1.D22 75.91,31.98 ; P1.D22 76.52,32.59 ; P1.D22 75.91,33.21 ; DGND1.1 63.25,64.06 ; DGND1.1 63.25,61.94 ; DGND1.1 62.19,63 ; DGND1.1 64.31,63 ; P1.H18 v1(70.13,37.67) ; P1.H18 70.83,38.29 ; P1.H18 71.44,37.67 ; P1.H18 70.83,37.06 ; P1.G4 72.09,56.07 ; P1.G4 72.09,54.84 ; P1.G4 71.48,55.45 ; P1.G4 v1(72.79,55.45) ; P1.D3 75.91,57.34 ; P1.D3 76.52,56.73 ; P1.D3 v1(75.21,56.73) ; P1.D3 75.91,56.11 ; 76.56,19.89 P1.C32 ; P1.C32 77.17,20.51 ; P1.C32 v1(77.87,19.89) ; P1.C32 77.17,19.28 ; P1.D10 75.91,48.45 ; P1.D10 v1(75.21,47.84) ; P1.D10 76.52,47.84 ; P1.D10 75.91,47.22 ; P1.H3 71.44,56.73 ; P1.H3 70.83,57.34 ; P1.H3 70.83,56.11 ; P1.H3 v1(70.13,56.73) ; P1.C36 v1(77.87,14.81) ; P1.C36 76.56,14.81 ; P1.C36 77.17,15.43 ; P1.C36 77.17,14.2 ; 76.56,40.22 P1.C16 ; P1.C16 77.17,39.6 ; P1.C16 v1(77.87,40.22) ; P1.C16 77.17,40.83 ; P1.G11 72.09,47.18 ; P1.G11 72.09,45.95 ; P1.G11 71.48,46.56 ; P1.G11 v1(72.79,46.56) ; P1.C12 77.17,45.91 ; P1.C12 76.56,45.3 ; P1.C12 v1(77.87,45.3) ; P1.C12 77.17,44.68 ; P1.G20 v1(72.79,35.13) ; P1.G20 71.48,35.13 ; P1.G20 72.09,34.52 ; P1.G20 72.09,35.75 ; 76.56,55.45 P1.C4 ; P1.C4 v1(77.87,55.45) ; P1.C4 77.17,56.07 ; P1.C4 77.17,54.84 ; 72.09,9.12 P1.G40 ; P1.G40 72.09,10.35 ; P1.G40 v1(72.88,9.73) ; P1.G40 71.48,9.73 ; P1.G17 v1(72.79,38.95) ; P1.G17 72.09,39.56 ; P1.G17 72.09,38.33 ; P1.G17 71.48,38.95 ; 77.17,11.66 77.17,12.28 ; 77.17,12.28 v1(77.87,12.28) ; 77.17,12.28 77.17,12.89 ; 77.17,12.28 76.56,12.28 ; P1.C13 77.17,44.64 ; P1.C13 v1(77.87,44.02) ; P1.C13 76.56,44.02 ; P1.C13 77.17,43.41 ; P1.D13 75.91,44.64 ; P1.D13 v1(75.21,44.02) ; P1.D13 76.52,44.02 ; P1.D13 75.91,43.41 ; 75.91,57.38 P1.D2 ; P1.D2 76.52,57.99 ; P1.D2 v1(75.21,57.99) ; 75.91,52.3 P1.D6 ; P1.D6 v1(75.21,52.91) ; P1.D6 76.52,52.91 ; P1.D6 75.91,53.53 ; 77.17,18.01 P1.C33 ; P1.C33 76.56,18.62 ; P1.C33 77.17,19.24 ; P1.C33 v1(77.87,18.62) ; P1.C1 v1(77.87,59.27) ; P1.C1 77.17,58.65 ; P1.C1 77.17,59.88 ; 72.09,42.14 P1.G14 ; P1.G14 72.09,43.37 ; P1.G14 71.48,42.76 ; P1.G14 v1(72.79,42.76) ; 75.91,39.6 P1.D16 ; P1.D16 v1(75.21,40.22) ; P1.D16 75.91,40.83 ; P1.D16 76.52,40.22 ; P1.C40 v1(77.87,9.73) ; P1.C40 77.17,10.35 ; P1.C40 77.17,9.12 ; P1.C40 76.56,9.73 ; 70.83,25.63 P1.H27 ; P1.H27 70.83,26.86 ; P1.H27 v1(70.13,26.25) ; P1.H27 71.44,26.25 ; 76.56,28.79 P1.C25 ; P1.C25 77.17,29.4 ; P1.C25 77.17,28.17 ; P1.C25 v1(77.87,28.79) ; 72.09,58.65 P1.G1 ; P1.G1 v1(72.88,59.27) ; P1.G1 72.09,59.88 ; P1.G1 71.48,59.27 ; 72.09,23.09 P1.G29 ; P1.G29 72.09,24.32 ; P1.G29 71.48,23.7 ; P1.G29 v1(72.79,23.7) ; 76.56,38.95 P1.C17 ; P1.C17 77.17,38.33 ; P1.C17 v1(77.87,38.95) ; P1.C17 77.17,39.56 ; 72.09,53.57 P1.G5 ; P1.G5 71.48,54.19 ; P1.G5 72.09,54.8 ; P1.G5 v1(72.79,54.19) ; P1.H24 71.44,30.05 ; P1.H24 70.83,29.44 ; P1.H24 v1(70.13,30.05) ; P1.H24 70.83,30.67 ; P1.C8 77.17,50.99 ; P1.C8 77.17,49.76 ; P1.C8 76.56,50.38 ; P1.C8 v1(77.87,50.38) ; P1.G8 v1(72.79,50.38) ; P1.G8 72.09,50.99 ; P1.G8 72.09,49.76 ; P1.G8 71.48,50.38 ; P1.H2 71.44,57.99 ; P1.H2 v1(70.13,57.99) ; P1.H2 70.83,58.61 ; P1.H2 70.83,57.38 ; P1.H36 71.44,14.81 ; P1.H36 v1(70.13,14.81) ; P1.H36 70.83,15.43 ; P1.H36 70.83,14.2 ; 75.91,12.93 75.91,13.54 ; 75.91,13.54 76.52,13.54 ; 75.91,13.54 75.91,14.16 ; 75.91,13.54 v1(75.21,13.54) ; 70.83,48.49 70.83,49.1 ; 70.83,49.1 70.83,49.72 ; 70.83,49.1 71.44,49.1 ; 70.83,49.1 v1(70.13,49.1) ; 70.83,21.82 P1.H30 ; P1.H30 70.83,23.05 ; P1.H30 71.44,22.43 ; P1.H30 v1(70.13,22.43) ; P1.G26 v1(72.79,27.52) ; P1.G26 72.09,26.9 ; P1.G26 72.09,28.13 ; P1.G26 71.48,27.52 ; 75.91,28.17 P1.D25 ; P1.D25 76.52,28.79 ; P1.D25 75.91,29.4 ; P1.D25 v1(75.21,28.79) ; P1.C21 77.17,34.48 ; P1.C21 77.17,33.25 ; P1.C21 76.56,33.87 ; P1.C21 v1(77.87,33.87) ; 72.09,12.28 v1(72.79,12.28) ; 72.09,12.28 72.09,11.66 ; 72.09,12.28 72.09,12.89 ; 72.09,12.28 71.48,12.28 ; 77.17,23.09 P1.C29 ; P1.C29 76.56,23.7 ; P1.C29 77.17,24.32 ; P1.C29 v1(77.87,23.7) ; 76.56,24.98 P1.C28 ; P1.C28 77.17,25.59 ; P1.C28 v1(77.87,24.98) ; P1.C28 77.17,24.36 ; P1.D39 75.91,11.62 ; P1.D39 76.52,11.01 ; P1.D39 v1(75.21,11.01) ; P1.D39 75.91,10.39 ; P1.D7 v1(75.21,51.65) ; P1.D7 75.91,52.26 ; P1.D7 75.91,51.03 ; P1.D7 76.52,51.65 ; 75.91,35.79 P1.D19 ; P1.D19 v1(75.21,36.41) ; P1.D19 75.91,37.02 ; P1.D19 76.52,36.41 ; P1.G32 72.09,20.51 ; P1.G32 71.48,19.89 ; P1.G32 v1(72.79,19.89) ; P1.G32 72.09,19.28 ; P1.C20 77.17,35.75 ; P1.C20 v1(77.87,35.13) ; P1.C20 77.17,34.52 ; P1.C20 76.56,35.13 ; 75.91,24.36 P1.D28 ; P1.D28 76.52,24.98 ; P1.D28 v1(75.21,24.98) ; P1.D28 75.91,25.59 ; DGND2.1 67.31,16 ; DGND2.1 66.25,17.06 ; DGND2.1 66.25,14.94 ; DGND2.1 65.19,16 ; 76.56,30.05 P1.C24 ; P1.C24 77.17,30.67 ; P1.C24 v1(77.87,30.05) ; P1.C24 77.17,29.44 ; P1.G35 72.09,16.7 ; P1.G35 72.09,15.47 ; P1.G35 v1(72.79,16.09) ; P1.G35 71.48,16.09 ; P1.H33 71.44,18.62 ; P1.H33 70.83,18.01 ; P1.H33 v1(70.13,18.62) ; P1.H33 70.83,19.24 ; 76.56,49.1 77.17,49.1 ; 77.17,49.1 77.17,48.49 ; 77.17,49.1 77.17,49.72 ; 77.17,49.1 v1(77.87,49.1) ; 71.48,31.32 P1.G23 ; P1.G23 72.09,31.94 ; P1.G23 v1(72.79,31.32) ; P1.G23 72.09,30.71 ; P1.H15 v1(70.13,41.48) ; P1.H15 70.83,42.1 ; P1.H15 70.83,40.87 ; P1.H15 71.44,41.48 ; 77.17,53.57 P1.C5 ; P1.C5 77.17,54.8 ; P1.C5 v1(77.87,54.19) ; P1.C5 76.56,54.19 ; P1.H21 70.83,34.48 ; P1.H21 v1(70.13,33.87) ; P1.H21 70.83,33.25 ; P1.H21 71.44,33.87
  vias: v1(55.12,49.62) v1(55.12,48.88) v1(55.25,35.62) v1(55.75,49.62) v1(56,35.62) v1(56,34.88) v1(56.5,49.62) v1(56.5,48.88) v1(56.75,35.62) v1(56.75,34.88) v1(57.42,65.61) v1(57.42,63.11) v1(57.42,50.61) v1(57.42,43.11) v1(57.42,38.11) v1(57.42,10.61) v1(57.5,32.5) v1(59.92,65.61) v1(59.92,63.11) v1(59.92,43.11) v1(59.92,40.61) v1(59.92,15.61) v1(61.12,17.38) v1(62.42,65.61) v1(62.42,60.61) v1(62.42,5.61) v1(64.12,25.62) v1(64.92,65.61) v1(64.92,63.11) v1(64.92,60.61) v1(64.92,58.11) v1(64.92,55.61) v1(64.92,50.61) v1(64.92,48.11) v1(64.92,33.11) v1(64.92,30.61) v1(64.92,28.11) v1(64.92,18.11) v1(64.92,8.11) v1(64.92,3.11) v1(67.42,65.61) v1(67.42,63.11) v1(67.42,60.61) v1(67.42,58.11) v1(67.42,55.61) v1(67.42,53.11) v1(67.42,43.11) v1(67.42,40.61) v1(67.42,38.11) v1(67.42,30.61) v1(67.42,28.11) v1(68.5,25.62) v1(69.92,63.11) v1(69.92,60.61) v1(69.92,58.11) v1(69.92,55.61) v1(69.92,43.11) v1(69.92,40.61) v1(69.92,28.11) v1(72.42,63.11) v1(72.42,60.61) v1(74.92,65.61) v1(74.92,55.61) v1(74.92,43.11) v1(74.92,38.11) v1(74.92,35.61) v1(74.92,28.11) v1(74.92,20.61) v1(74.92,8.11) v1(74.92,3.11) v1(77.42,65.61) v1(77.42,63.11) v1(77.42,60.61) v1(77.42,8.11) v1(77.42,3.11) v1(79.92,65.61) v1(79.92,63.11) v1(79.92,60.61) v1(79.92,58.11) v1(79.92,55.61) v1(79.92,53.11) v1(79.92,25.61) v1(79.92,23.11) v1(79.92,20.61) v1(79.92,18.11) v1(79.92,13.11) v1(79.92,10.61) v1(79.92,8.11) v1(79.92,5.61) v1(79.92,3.11)
